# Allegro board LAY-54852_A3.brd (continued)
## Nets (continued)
GND: BH901.1 BH1901.1 BH1902.1 BH1903.1 BH1904.1 BT1001.2(-) C10.2 C22.2 C23.2 C38.2 C101.2 C102.2 C104.2 C105.2 C106.2 C107.2 C108.2 C109.2 C110.2 C111.2 C115.2 C116.2 C118.2 C119.2 C129.2 C130.2 C131.2 C132.2 C133.2 C136.2 C137.2 C138.2 C139.2 C140.2 C142.2 C143.2 C144.2 C145.2 C146.2 C151.2 C152.2 C153.2 C155.2 C201.2 C202.2 C203.2 C204.2 C205.2 C206.2 C207.2 C208.2 C209.2 C210.2 C211.2 C212.2 C213.2 C214.2 C215.2 C216.2 C217.2 C218.2 C219.2 C220.2 C221.2 C222.2 C301.2 C302.2 C303.2 C304.2 C305.2 C306.1 C307.2 C309.1 C401.2 C402.2 C403.2 C404.2 C405.2 C406.2 C408.2 C409.2 C410.2 C411.2 C412.2 C413.1 C414.2 C418.2 C501.2 C502.2 C503.2 C504.2 C505.2 C506.2 C507.2 C508.2 C509.2 C510.2 C511.2 C512.2 C513.2 C514.2 C515.2 C516.2 C517.2 C518.2 C519.2 C520.2 C521.2 C701.1 C702.1 C703.2 C704.2 C705.2 C706.2 C707.2 C708.2 C709.1 C710.2 C711.2 C712.1 C713.1 C714.2 C715.2 C716.2 C717.2 C718.1 C719.2 C720.2 C721.1 C722.2 C723.2 C724.1 C725.2 C726.2 C727.2 C728.2 C729.2 C730.2 C731.2 C801.2 C802.2 C803.2 C804.2 C805.2 C806.2 C807.2 C808.2 C809.2 C902.2 C903.2 C904.2 C905.2 C906.2 C907.2 C908.2 C910.2 C911.2 C912.2 C913.2 C914.2 C915.2 C916.2 C917.2 C918.2 C920.2 C921.2 C922.2 C923.2 C928.2 C930.2 C931.2 C932.2 C933.2 C955.2 C956.2 C1019.2 C1020.2 C1021.2 C1022.2 C1023.2 C1024.2 C1201.2 C1202.2 C1204.2 C1205.2 C1207.2 C1208.2 C1209.2 C1210.2 C1217.2 C1219.2 C1221.1 C1223.2 C1227.1 C1230.2 C1231.2 C1301.2 C1302.2 C1303.2 C1304.2 C1307.2 C1308.2 C1309.2 C1310.2 C1317.2 C1318.2 C1319.2 C1320.2 C1322.2 C1323.2 C1324.2 C1325.2 C1401.2 C1402.2 C1403.2 C1404.2 C1405.2 C1406.2 C1407.2 C1408.2 C1409.2 C1410.2 C1411.2 C1412.2 C1413.2 C1414.2 C1415.2 C1416.2 C1417.2 C1418.2 C1419.2 C1420.2 C1421.2 C1422.2 C1423.2 C1424.2 C1425.2 C1426.2 C1427.2 C1428.2 C1429.2 C1430.2 C1431.2 C1432.2 C1433.2 C1434.2 C1435.2 C1436.2 C1437.2 C1460.2 C1461.2 C1462.2 C1501.2 C1502.2 C1503.2 C1504.1 C1505.2 C1506.2 C1507.2 C1508.2 C1509.2 C1703.2 C1704.2 C1719.2 C1720.2 C1721.2 C1722.2 C1723.2 C1724.2 C1725.2 C1726.2 C1727.2 C1728.2 C1729.2 C1730.2 C1731.2 C1732.2 C1733.2 C1734.2 C1735.2 C1736.2 C1737.1 C1738.2 C1739.2 C1740.2 C1741.2 C1742.2 C1743.2 C1744.1 C1745.2 C1746.2 C1747.2 C1748.2 C1750.2 C1751.2 C1752.2 C1754.2 C1755.2 C1756.2 C1757.2 C1762.2 C1763.2 C1764.2 C1765.2 C1771.2 C1772.2 C1787.1 C1789.2 C1792.2 D302.A D601.C(CATHODE) D901.A D902.C(CATHODE) D1003.2(A2) D1004.2(A2) D1005.2(C2) D1006.2(C2) D1007.2(C2) D1008.2(C2) D1009.2(C2) D1010.2(C2) D1410.C(CATHODE) D1411.C(CATHODE) D1414.C(CATHODE) D1503.3(COM_CATHODE) J301.A12 J301.B12 J301.SH1 J301.SH2 J301.SH3 J301.SH4 J901.2 J1002.6(VSS) J1002.10 J1002.11 J1002.12 J1002.13 J1101.A1 J1101.A12 J1101.B1 J1101.B12 J1101.SH1 J1101.SH2 J1101.SH3 J1101.SH4 J1201.2 J1401.6 J1401.9 J1401.14 J1401.20 J1401.25 J1401.30 J1401.34 J1401.39 J1403.5 J1403.6(B3) J1406.7 J1406.8(B4) J1501.4 J1704.3 J1704.5 J1707.1 J1707.7 J1707.18 J1707.33 J1707.39 J1707.45 J1707.51 J1707.57 J1707.63 J1707.69 J1707.75 J1708.A1 J1708.A12 J1708.B1 J1708.B12 J1708.SH1 J1708.SH2 J1708.SH3 J1708.SH4 Q301.2(SOURCE) Q302.2(SOURCE) Q901.2(SOURCE) Q902.2(SOURCE) Q1401.2(SOURCE) Q1402.2(SOURCE) Q1403.2(SOURCE) Q1404.2(SOURCE) Q1405.2(SOURCE) Q1407.2(SOURCE) Q1408.2(SOURCE) Q1409.2(SOURCE) Q1410.2(SOURCE) Q1411.2(SOURCE) R14.2 R201.2 R204.2 R207.1 R208.1 R303.2 R313.2 R353.1 R354.1 R405.2 R412.1 R413.1 R415.2 R418.2 R423.2 R424.2 R507.2 R508.2 R509.1 R519.2 R520.2 R521.2 R522.2 R523.2 R524.2 R525.2 R526.2 R527.2 R609.2 R610.2 R611.2 R612.2 R718.2 R741.2 R742.2 R743.1 R751.2 R752.2 R827.2 R838.2 R839.2 R840.2 R841.2 R910.2 R911.2 R954.2 R1078.1 R1079.1 R1222.2 R1330.2 R1409.1 R1410.1 R1412.1 R1433.2 R1434.2 R1435.2 R1436.2 R1437.2 R1446.2 R1447.2 R1448.2 R1462.2 R1463.2 R1488.2 R1489.2 R1490.2 R1706.2 R1717.2 R1719.2 R1728.2 R1738.2 R1745.2 R1746.2 R1747.2 R1750.2 R1753.2 R1754.2 R1759.2 R1761.2 R1770.2 R1771.2 R1772.2 R1781.2 R1782.2 R1795.1 R1798.2 R1800.2 R1801.2 R1810.2 R1812.1 R1821.2 R1823.2 R1824.2 SW1401.1 SW1401.2 SW1402.1 SW1402.2 TP615.1(TP) TP617.1(TP) TP1412.1(PIN1) TP1901.1(TP) TP1902.1(PIN1) TP1903.1(PIN1) TP1904.1(PIN1) TP1905.1(TP) TP1907.1(PIN1) TP1908.1(PIN1) TP1909.1(PIN1) TVS901.1 TVS1201.1 TVS1202.1 TVS1203.1 TVS1204.1 TVS1401.1 U58.2 U101.A1 U101.A17 U101.C6 U101.C8 U101.C12 U101.C14 U101.D3 U101.D15 U101.E12 U101.F3 U101.F6 U101.F8 U101.F10 U101.F15 U101.G6 U101.G12 U101.H3 U101.H9 U101.H15 U101.J6 U101.J12 U101.K3 U101.K9 U101.L7 U101.M3 U101.M6 U101.M8 U101.M10 U101.M12 U101.M15 U101.N10 U101.P3 U101.P15 U101.R4(VSS9) U101.R6 U101.R8 U101.R10 U101.R12 U101.R14 U101.U1 U101.U17 U201.A3 U201.A10 U201.AB3 U201.AB5 U201.AB8 U201.AB10 U201.C1 U201.C5 U201.C8 U201.C12 U201.D2 U201.D4 U201.D9 U201.D11 U201.E1 U201.E5 U201.E8 U201.E12 U201.G1 U201.G3 U201.G5 U201.G8 U201.G10 U201.G12 U201.J1 U201.J3 U201.J10 U201.J12 U201.K2 U201.K4 U201.K9 U201.K11 U201.N2 U201.N4 U201.N9 U201.N11 U201.P1 U201.P3 U201.P10 U201.P12 U201.T1 U201.T3 U201.T5 U201.T8 U201.T10 U201.T12 U201.V1 U201.V5 U201.V8 U201.V12 U201.W2 U201.W4 U201.W9 U201.W11 U201.Y1 U201.Y5 U201.Y8(VSS_Y8) U201.Y12 U301.17 U302.C3 U302.D3 U302.E3 U303.B3 U303.D3 U401.5 U401.17 U402.A4 U402.B2 U402.B3 U402.B4 U402.B5 U403.B1(GND) U404.2(V-) U405.3 U411.B3 U411.D3 U501.A6 U501.C4 U501.E7 U501.G5 U501.H10 U501.J5 U501.K8 U501.N2 U501.N5 U501.P4 U501.P6 U502.3 U502.8 U503.3 U503.8 U701.5 U701.43 U701.57 U801.25(VSS) U801.26 U801.33 U802.3 U803.6 U804.6 U805.6 U901.2 U901.10 U902.4 U904.6 U905.6 U906.6 U908.6 U915.A2 U915.B1 U1004.7(VSS) U1004.17 U1202.2 U1301.5 U1301.6 U1301.7 U1301.8 U1302.3 U1302.5 U1302.6 U1302.7 U1302.8 U1304.5 U1304.6 U1304.7 U1304.8 U1305.3 U1305.5 U1305.6 U1305.7 U1305.8 U1306.2 U1307.3 U1308.3 U1309.3 U1401.6 U1401.7 U1403.B1(GND) U1404.10 U1404.11 U1405.2(VSS) U1406.4 U1407.3 U1408.6 U1409.9(VSS) U1409.23 U1409.24 U1409.25 U1410.2 U1501.2 U1702.6 U1702.13 U1706.1 U1706.5 U1706.10 U1706.11 U1706.13 U1706.15 U1706.25 U1706.35 U1706.47 U1706.51 U1707.3 U1708.B1 U1709.B1 U1709.C1 U1709.C7 U1709.D7 U1709.F3 U1709.G5 U1710.10 U1712.41 U1713.10 U1713.11 U1714.2 X1401.2 X1401.4 Y401.2 Y401.4 Y501.2 Y501.4
GND_CHASSIS: C1744.2 J501.10 J501.SH1 J501.SH2 R509.2
VBUS1_DET_3V3: R301.1 U101.B3
VBUS_DBG: J1708.A4 J1708.A9 J1708.B4(VBUS4) J1708.B9 L1702.1 TVS1401.2(A2)
VBUS_IN: C302.1 C303.1 C905.1 C931.1 C932.1 C933.1 C1735.1 R302.2 R904.1 R905.1 R1757.2 R1773.2 R1774.2 U901.1
VBUS_OVLO_TH: R304.2 R1759.1 U302.B3
VBUS_USB_DBG: C1409.1 C1725.1 C1726.1 L1702.2 U1410.1 U1410.3
VCC_3V6: C907.1 R908.1 U901.9
VCC_FT_1V8: C1408.1 C1723.1 C1724.1 L1404.1 U1706.12 U1706.37 U1706.64
VCC_FT_3V3: C1417.1 C1418.1 C1419.1 C1420.1 C1423.1 C1424.1 C1425.1 C1429.1 C1432.1 C1433.1 C1434.1 C1435.1 C1460.1 C1461.1 C1719.1 C1720.1 D1703.C D1704.C L1703.1 L1704.1 R1053.1 R1056.1 R1421.2 R1450.1 R1451.1 R1452.1 R1453.1 R1465.1 R1467.1 R1468.1 R1485.1 R1486.1 R1726.2 R1727.2 R1729.2 R1730.2 R1733.2 R1734.1 R1735.1 R1736.1 R1737.1 R1742.1 R1748.1 R1815.1 R1816.1 U1404.3 U1405.6 U1406.8(VCC) U1407.6 U1408.1 U1409.21 U1706.20 U1706.31 U1706.42 U1706.50 U1706.56 U1713.2(VCCB)
VDD_1V8: C23.1 C115.1 C116.1 C201.1 C202.1 C203.1 C204.1 C205.1 C209.1 C504.1 C505.1 C506.1 C507.1 C719.1 C720.1 C802.1 C922.1 C923.1 C1436.1 C1437.1 C1448.1 C1756.1 D1407.A J1405.1 L102.1 L705.2 L1201.1 L1301.1 Q1406.2(SOURCE) R64.2 R65.2 R501.1 R502.1 R510.1 R746.2 R951.1 R952.1 R956.2 R1441.1 R1459.1 R1460.1 R1756.1 R1767.1 R1779.1 TP707.1(TP) U101.L6 U101.L9 U101.L11 U201.F1 U201.F12 U201.G4 U201.G9 U201.T4 U201.T9 U201.U1 U201.U12 U501.C6 U501.M4 U501.N4 U501.P3 U501.P5 U701.14 U802.5 U904.11 U905.11(VCCB) U906.1 U908.1 U1408.11
VDD_3V3: C22.1 C118.1 C119.1 C155.1 C307.1 C411.1 C501.1 C502.1 C503.1 C714.1 C715.1 C724.2 C801.1 C804.1 C805.1 C806.1 C807.1 C808.1 C809.1 C920.1 C921.1 C955.1 C956.1 C1201.1 C1202.1 C1231.1 C1319.1 C1320.1 C1324.1 C1325.1 C1401.1 C1403.1 C1404.1 C1412.1 C1426.1 C1427.1 C1703.1 C1704.1 C1721.1 C1722.1 C1755.1 C1789.1 C1792.1 D1501.A D1502.A D1703.A J1406.1 J1406.2 L501.1 L502.1 L704.2 L1405.1 R213.1 R306.1 R307.1 R308.1 R309.1 R431.1 R505.1 R506.1 R601.1 R602.1 R603.1 R604.1 R613.1 R705.1 R801.1 R802.1 R804.1 R808.1 R817.1 R863.1 R913.2 R923.1 R935.1 R950.1 R1054.1 R1075.1 R1076.1 R1080.1 R1081.1 R1202.1 R1203.1 R1221.1 R1333.1 R1402.1 R1403.1 R1404.1 R1405.1 R1406.1 R1407.1 R1408.1 R1420.1 R1440.1 R1502.1 R1718.2 R1762.1 R1765.1 R1768.1 R1775.1 R1813.1 R1827.1 TP608.1(TP) TP706.1(TP) U101.E8 U101.H13 U101.K13 U301.3(VDD) U401.3(VDD) U501.E6 U501.F5 U501.J10 U501.K9 U701.21 U701.22 U801.27 U801.31 U803.14(VDD) U804.14(VDD) U805.14(VDD) U904.1 U905.1 U906.11(VCCB) U908.11(VCCB) U915.A1(VCC) U1306.1 U1307.5 U1308.5 U1401.5(VDDIO) U1401.8 U1404.2(VCCB) U1702.14(VDD) U1709.A3 U1709.G3 U1713.3 U1714.3
VDD_5V: C309.2 C413.2 C910.1 C928.1 C930.1 C1219.1 C1733.1 D1402.2 R912.1 R914.1 R1501.2 R1503.2 R1766.1 TP904.1(PIN1) U58.5 U301.12 U401.12 U404.5 U902.7(VOUT) U1202.3
VDD_ANA_0V8: C130.1 C131.1 C132.1 C133.1 R871.2 TP712.1(TP) U101.C4 U101.F13 U101.M13
VDD_ANA_1V8: C142.1 C143.1 C144.1 C145.1 C146.1 L102.2 R111.2 U101.E6 U101.F12 U101.L12 U101.N8
VDD_COIN_3V: BT1001.1 R1072.2 R1082.1
VDD_SNVS_0V8: C102.1 U101.C10
VDD_SOC_0V85: C104.1 C105.1 C106.1 C107.1 C108.1 C109.1 C110.1 C111.1 C707.1 C708.1 L702.2 R701.1 R709.1 R711.2 TP703.1(TP) U101.G7 U101.G9 U101.G11 U101.H7 U101.H11 U101.K7 U101.K11
VINT: C706.1 U701.4
ADC_IN0: C1413.1 R1442.2 TP408.1(PIN1) U101.B8
ADC_IN1: C1414.1 R1444.2 TP409.1(PIN1) U101.A8
ADCDAT1: R1208.2 U1709.D2
AUD_5V: L1205.1 U1202.1 U1202.5(OUT2)
AUD_NINT: R845.2 R1204.1 R1221.2
AUD_PWREN: R831.2 R1219.1
AUD_SCL: R1212.2 U1709.F1
AUD_SDA: R1211.2 U1709.E2
BCLK1: R1206.2 U1709.E1
BT_MODE0: R1731.2 U1404.6
BT_MODE1: R1732.2 U1404.7
BT_MODE2: R1418.2 U1404.8
BT_MODE3: R1419.2 U1404.9
BUF_POR: R808.2 R811.1 U802.4(Y)
BYPASS1: C1737.2 U401.4
CAN1_RX: R1509.1 U1702.4
CAN1_TX: R1508.1 U1702.1
CAN_H: C1504.2 D1503.1 J1501.2 L1501.2 R1504.2 R1507.2
CAN_L: C1509.1 D1503.2 J1501.3 L1501.3 R1510.2 R1511.1
CAN_RX: R1505.2 R1509.2 U1501.4
CAN_STBY: R837.2 R1512.2 U1501.8
CAN_TX: R1506.2 R1508.2 U1501.1
CAN_VDD_5V: C1501.1 C1502.1 R1501.1 U1501.3
CAN_VIO_3V3: C1503.1 R1502.2 R1512.1 U1501.5(VIO)
CANH: L1501.1 R1507.1 U1501.7
CANL: L1501.4 R1510.1 U1501.6
CLKIN1: R415.1 TP411.1(PIN1) U101.A6
CLKIN2: R423.1 TP412.1(PIN1) U101.B6
CLKOUT2: TP1948.1(PIN1) U1709.E4
CLKOUT5: TP1950.1(PIN1) U1709.G6
CON_JTAG_NRST: D1408.C D1409.C J1704.10(B5) R1461.2
CPCA: C1761.1 U1709.B6
CPCB: C1761.2 U1709.B7
CPVOUTN: C1762.1 U1709.A7
CPVOUTP: C1763.1 U1709.A6
DACDAT1: R1207.2 U1709.D1
DBG_ACC: TP1926.1(PIN1) U401.9
DCIN_15V: J901.1 R905.2
DMIC_PDM_CLK: U1309.2 U1702.16
DMIC_PDM_DATA0: U1307.4(Y) U1702.3
DMIC_PDM_DATA1: U1308.4(Y) U1702.9
DRAM_CA0_A: TP219.1(PIN1) U101.F1 U201.H2
DRAM_CA1_A: U101.E2 U201.J2
DRAM_CA2_A: U101.D2 U201.H9
DRAM_CA3_A: U101.C1 U201.H10
DRAM_CA4_A: U101.B2 U201.H11
DRAM_CA5_A: U101.A2 U201.J11
DRAM_CK_C_A: R205.2 U101.B1 U201.J9
DRAM_CK_T_A: R205.1 U101.C2 U201.J8
DRAM_CKE0_A: R207.2 U101.G1 U201.J4
DRAM_CKE1_A: R208.2 U101.F2 U201.J5
DRAM_DATA0_A: TP206.1(PIN1) U101.L2 U201.F4
DRAM_DATA1_A: TP207.1(PIN1) U101.L1 U201.E4
DRAM_DATA2_A: TP208.1(PIN1) U101.K2 U201.C4
DRAM_DATA3_A: TP209.1(PIN1) U101.K1 U201.B4
DRAM_DATA4_A: TP202.1(PIN1) U101.J1 U201.B2
DRAM_DATA5_A: TP203.1(PIN1) U101.H2 U201.C2
DRAM_DATA6_A: TP204.1(PIN1) U101.H1 U201.E2
DRAM_DATA7_A: TP205.1(PIN1) U101.G2 U201.F2
DRAM_DATA8_A: TP212.1(PIN1) U101.T2 U201.E11
DRAM_DATA9_A: TP213.1(PIN1) U101.U2 U201.F11
DRAM_DATA10_A: TP211.1(PIN1) U101.T1 U201.C11
DRAM_DATA11_A: TP210.1(PIN1) U101.R2 U201.B11
DRAM_DATA12_A: TP216.1(PIN1) U101.N1 U201.C9
DRAM_DATA13_A: TP217.1(PIN1) U101.N2 U201.B9
DRAM_DATA14_A: TP215.1(PIN1) U101.M2 U201.E9
DRAM_DATA15_A: TP214.1(PIN1) U101.M1 U201.F9
DRAM_DMI0_A: TP201.1(PIN1) U101.J2 U201.C3
DRAM_DMI1_A: U101.R1 U201.C10
DRAM_NCS0_A: TP218.1(PIN1) U101.D1 U201.H4
DRAM_NCS1_A: U101.E1 U201.H3
DRAM_NRESET: R102.1 R201.1 U101.F4 U201.T11
DRAM_SDQS0_C_A: U101.K4 U201.E3
DRAM_SDQS0_T_A: U101.M4 U201.D3
DRAM_SDQS1_C_A: U101.P2 U201.E10
DRAM_SDQS1_T_A: U101.P1 U201.D10
DRAM_ZN: R204.1 U101.H4
DRAM_ZQ0: R209.2 U201.A5
EMMC_VDDIM: C508.1 C509.1 U501.C2
EN_SNK: R411.2 U402.F1
EN_SRC: R410.2 U402.G1
ENET1_MDC: R503.1 U101.T8
ENET1_MDIO: R1779.2 R1780.1 U101.U7
ENET1_NINT: R505.2 U804.16 U1712.31
ENET1_NRST: R506.2 R826.2 U1712.12
ENET1_RD0: R517.2 R526.1 U101.U5 U1712.25
ENET1_RD1: R518.2 R527.1 U101.T6 U1712.24
ENET1_RD2: R514.2 R522.1 U101.U6 U1712.23
ENET1_RD3: R515.2 R523.1 U101.T7 U1712.22
ENET1_RX_CTL: R525.1 U101.T5 U1712.26
ENET1_RXC: C519.1 R516.2 R524.1 U101.U4 U1712.27
ENET1_TD0: TP221.1(PIN1) U101.U9 U1712.18
ENET1_TD1: U101.R9 U1712.17
ENET1_TD2: U101.U10 U1712.16
ENET1_TD3: U101.T10 U1712.15
ENET1_TX_CTL: U101.T9 U1712.19
ENET1_TXC: TP220.1(PIN1) U101.U8 U1712.20
ETH1_10/100M_LINK/ACTIVE: J501.13 R504.1
ETH1_1000M_LINK/ACTIVE: J501.11 R507.1 R529.1
ETH1_AVDD1V0: C515.1 C516.1 C517.1 C518.1 R530.2 U1712.3 U1712.8 U1712.38
ETH1_AVDD3V3: C1742.1 C1743.1 L502.2 U1712.11 U1712.40
ETH1_CLK125_OUT: TP1933.1(PIN1) U1712.35
ETH1_CT: C1738.1 J501.1
ETH1_DVDD1V0: C513.1 C514.1 R531.2 U1712.21
ETH1_DVDD3V3: C1739.1 C1740.1 L501.2 R512.1 R513.1 R529.2 U1712.29
ETH1_LED0/CFG_EXT: R504.2 R512.2 R519.1 U1712.32
ETH1_LED1/CFGLDO0: C520.1 J501.14 R521.1 U1712.33
ETH1_LED2/CFGLDO1: C521.1 J501.12 R513.2 R520.1 U1712.34
ETH1_TRX0_N: J501.3 U503.2 U503.9 U1712.2
ETH1_TRX0_P: J501.2 U503.1 U503.10(NC4) U1712.1
ETH1_TRX1_N: J501.5 U503.5 U503.6 U1712.5
ETH1_TRX1_P: J501.4 U503.4 U503.7 U1712.4
ETH1_TRX2_N: J501.7 U502.2 U502.9 U1712.7
ETH1_TRX2_P: J501.6 U502.1 U502.10(NC4) U1712.6
ETH1_TRX3_N: J501.9(TRD4-) U502.5 U502.6 U1712.10
ETH1_TRX3_P: J501.8 U502.4 U502.7 U1712.9
ETH1_VDD1V0: C511.1 C512.1 R530.1 R531.1 U1712.30
ETH1_VDDIO: C1745.1 C1746.1 R510.2 R514.1 R515.1 R516.1 R517.1 R518.1 U1712.28
ETH1_XTALI: C510.1 R511.2 U1712.36 Y501.3
ETH1_XTALO: C1741.1 R511.1 U1712.37(XTAL_OUT/ EXT_CLK) Y501.1
EXP3V3_EN: R858.2 R1825.1
EXP5V_EN: R16.1 R806.2
EXP_3V3: C1402.1 C1405.1 L1401.1 U1714.1 U1714.5(OUT2)
EXP_5V: C38.1 C1406.1 C1407.1 L1402.2 U58.1(OUT)
EXP_GPIO_IO08: J1401.24 U805.1
EXP_GPIO_IO09: J1401.21 U805.4
EXP_GPIO_IO10: J1401.19 U805.8
EXP_GPIO_IO11: J1401.23 U805.11
EXP_GPIO_IO12: J1401.32 R1438.1 U803.1
EXP_GPIO_IO16: R856.2 R1829.1 U804.1
EXP_GPIO_IO17: J1401.11 U804.4
EXP_GPIO_IO18: R855.2 R1829.2 U803.4
EXP_GPIO_IO19: J1401.35 R745.2 U803.8
EXP_GPIO_IO20: J1401.38 U803.11
EXP_GPIO_IO21: J1401.40 U804.8
EXP_NIRQ: R813.1 U101.T4
EXP_SEL: R836.2 R838.1 U803.15 U804.15 U805.15
EXT1_PWREN: R825.2 R922.1
FRS_EN: U401.1 U402.B6
FT_BMODE_DIR: R1728.1 U1404.4 U1404.5 U1409.14
FT_BOOT_MODE0: R1731.1 U1409.1
FT_BOOT_MODE1: R1732.1 U1409.2
FT_BOOT_MODE2: R1418.1 U1409.3
FT_BOOT_MODE3: R1419.1 U1409.4
FT_EECLK: R1428.2 U1706.62
FT_EECS: R1740.2 U1706.63
FT_EEDATA: R1739.2 U1706.61
FT_IO_NINT1: R1487.1 U1706.30
FT_IOEXP2_SCL: R1470.2 U1409.19
FT_IOEXP2_SDA: R1469.2 U1409.20
FT_NPWREN: R1464.1 R1749.1 TP1407.1(PIN1) U1706.60
FT_NSUSPEND: R1744.1 TP1408.1(PIN1) U1706.36
FT_ONOFF: R1746.1 U1406.3 U1409.12
FT_OSCI: C1428.1 U1706.2 X1401.1
FT_OSCO: C1430.1 U1706.3 X1401.3
FT_POR_B: R1747.1 U1406.6 U1409.10
FT_RC_SEL: R1751.1 U1409.13
FT_SCL: R1470.1 R1726.1 TP1912.1(PIN1) U1706.26
FT_SD_CD: R1053.2 U1409.16 U1707.1
FT_SD_PWREN: R1056.2 R1057.1 U1409.15
FT_SDA: R1469.1 R1727.1 TP1913.1(PIN1) U1706.27 U1706.28
FT_SYS_NRST: R1745.1 U1406.1 U1409.11
FT_TST0: R1455.1 U1706.21
FT_TST1: R1457.1 U1706.22
FT_TST2: R1456.1 U1706.23
FT_TST3: R1458.1 U1706.24
FT_USB_DN: U1403.C1 U1706.7
FT_USB_DP: U1403.C2 U1706.8
FTA_TCK: U1408.2 U1706.16
FTA_TDI: U1408.3 U1706.17
FTA_TDO: U1408.5 U1706.18
FTA_TMS: U1408.4 U1706.19
FTC_RXD: D1404.C(CATHODE) R1819.1 U1706.39
FTC_TXD: D1403.C(CATHODE) R1817.1 U1706.38
FTD_CTS: TP1406.1(PIN1) U1706.54
FTD_RTS: TP1405.1(PIN1) U1706.53
FTD_RXD: D1405.C(CATHODE) R1820.1 U1706.52
FTD_TXD: D1406.C(CATHODE) R1818.1 U1706.48
GPIO_IO00: J1401.27 R1415.2 U101.B16
GPIO_IO01: J1401.28 R1417.2 U101.B17
GPIO_IO02: J1401.3 R1414.2 U101.C16
GPIO_IO03: J1401.5 R1416.2 U101.C17
GPIO_IO04: J1401.7 R1429.1 U101.D16
GPIO_IO05: J1401.29 U101.D17
GPIO_IO06: J1401.31 U101.E16
GPIO_IO07: J1401.26 U101.E17
GPIO_IO08: U101.K14 U805.2
GPIO_IO09: U101.F16 U805.5
GPIO_IO10: U101.F17 U805.7
GPIO_IO11: U101.G16 U805.10
GPIO_IO12: U101.F14 U803.2
GPIO_IO13: J1401.33 R1439.1 U101.G17
GPIO_IO14: J1401.8 U101.H16
GPIO_IO15: J1401.10 U101.H17
GPIO_IO16: U101.J16 U804.2
GPIO_IO17: U101.K15 U804.5
GPIO_IO18: U101.M14 U803.5
GPIO_IO19: U101.J17 U803.7
GPIO_IO20: U101.K16 U803.10
GPIO_IO21: U101.K17 U804.7
HP_DET: R812.2 R1822.1
HP_J_D: J1201.5 R1202.2 R1822.2 TVS1203.2(A2)
HP_J_L: C1771.1 J1201.4 L1202.2 TVS1202.2(A2)
HP_J_R: C1772.1 J1201.3 L1203.2 TVS1204.2(A2)
HP_MICIN: C1788.2 J1201.1 R1809.2 TVS1201.2(A2)
HPOUTL: C1769.1 L1202.1 R1823.1 U1709.B5
HPOUTR: C1770.1 L1203.1 R1810.1 U1709.A5
I2C1_SCL: R163.2 R307.2 R433.1 R717.1 R828.1 R1008.1 R1212.1 R1443.1 U101.A12
I2C1_SCLL: J1707.60 R65.1 R713.2 R930.2
I2C1_SDA: R164.2 R306.2 R432.1 R719.1 R830.1 R1009.1 R1211.1 R1445.1 U101.B12
I2C1_SDAL: J1707.58 R64.1 R712.2 R931.2
I2C2_SCL: R309.2 R714.1 R820.1 U101.A11
I2C2_SDA: R308.2 R715.1 R824.1 U101.B11
I2C3_SCL: R1015.1 R1405.2 R1413.1 R1417.1
I2C3_SDA: R1016.1 R1406.2 R1411.1 R1415.1
I2C4_SCL: R1017.1 R1407.2 R1416.1
I2C4_SDA: R1018.1 R1408.2 R1414.1
I3C1_SCL: R163.1 R861.1 R1404.2 R1413.2 U1401.13
I3C1_SDA: R164.1 R862.1 R1401.2 R1403.2 R1411.2 U1401.14
I3C_PUR: R1401.1 TP1401.1(PIN1)
I3C_TEMP_NINT: R744.2 R860.2
I.MX_SPI_CLK/UART_RTSO: R944.2 U905.8 U906.4
I.MX_SPI_CS/UART_TXD: R938.2 R945.2 U905.10 U906.2
I.MX_SPI_MISO/UART_RXD: R943.2 U905.7 U906.5
I.MX_SPI_MOSI/UART_CTSI: R941.2 R942.2 U905.9 U906.3
ILIM_5V_VBUS: TP1927.1(PIN1) U401.6
IMU_INT1: D1401.A U804.9
IN1R: C1787.2 U1709.D4
IN3R: C1788.1 U1709.F6
IOEXP_IO22: R854.1
IOEXP_IO23: R853.2
IOEXP_IO24: J1401.18(B9) R851.2
IOEXP_IO25: J1401.22 R850.2
IOEXP_IO27: J1401.13 R852.2
JTAG_TCK: J1704.4 R405.1 R416.1 TP1922.1(PIN1) U101.U3 U1408.10
JTAG_TDI: J1704.8 R417.1 R1460.2 TP1920.1(PIN1) U101.P8 U1408.9
JTAG_TDO: J1704.6 R414.1 TP1923.1(PIN1) U101.T3 U1408.7
JTAG_TMS: J1704.2 R419.1 R1459.2 TP1921.1(PIN1) U101.P6 U1408.8(YB3)
LD_I2C_SCL: R420.1 U402.B1
LD_I2C_SDA: R421.1 R434.1 U402.C1
LD_NFLT: R1775.2 R1776.1 U401.11
LD_NINT: R1776.2 U402.D1
LED_B: Q1401.3 R1424.2
LED_G: Q1402.3 R1423.2
LED_R: Q1403.3 R1425.2
LPD4/X_VDD2_1V1: C136.1 C137.1 C138.1 C139.1 C140.1 C206.1 C207.1 C208.1 C210.1 C211.1 C212.1 C213.1 C214.1 C722.1 C723.1 L706.2 R210.1 R702.1 TP708.1(TP) U101.K5 U101.M5 U101.N6 U101.P4 U201.A4 U201.A9 U201.AB4 U201.AB9 U201.F5 U201.F8 U201.H1 U201.H5 U201.H8 U201.H12 U201.K1 U201.K3 U201.K10 U201.K12 U201.N1 U201.N3 U201.N10 U201.N12 U201.R1 U201.R5 U201.R8 U201.R12 U201.U5 U201.U8 U701.52
LPD4/X_VDDQ_0V6: C151.1 C152.1 C153.1 C215.1 C216.1 C217.1 C218.1 C219.1 C220.1 C221.1 C222.1 R209.1 R211.2 R702.2 R704.2 TP702.1(TP) U101.F5 U101.H5 U201.AA3 U201.AA5 U201.AA8 U201.AA10 U201.B3 U201.B5 U201.B8 U201.B10 U201.D1 U201.D5 U201.D8 U201.D12 U201.F3 U201.F10 U201.U3 U201.U10 U201.W1 U201.W5 U201.W8 U201.W12
LPD4X_VDDQ_0V6: C703.1 C705.1 L701.2 R704.1 U701.44
LRCLK1: R1205.2 U1709.D3
LS_OE: R935.2 R1812.2 U905.12 U906.12
M2_LED1#: D1705.C(CATHODE) J1707.6
M2_LED2#: D1706.C(CATHODE) J1707.16
M2_NALERT: R818.2 R932.2 R936.2
M2_NDIS1: J1707.56 R835.2 R903.1
M2_NDIS2: J1707.54(W\_\D\I\S\A\B\L\E\2\) Q902.1 R832.2 R953.1
M2_NRST: J1707.52 R833.2
M2_PCM_CLK: J1707.8 R946.2
M2_PCM_IN: J1707.12 R949.2
M2_PCM_OUT: J1707.14 R948.2
M2_PCM_SYNC: J1707.10 R947.2
M2_PWRON: C1754.1 R903.2 R922.2 R950.2 R1781.1 U1710.5
M2_SD_NWAKE: J1707.21 R1793.2 TP918.1(PIN1)
M2_UART_NWAKE: J1707.20 R809.2 R924.2
M2_USB_DN: J1707.5 TP1935.1(PIN1)
M2_USB_DP: J1707.3 TP1934.1(PIN1)
M33_NMI: TP1701.1(PIN1) U1702.8
MIC/CAN_SEL: R829.2 R1706.1 U1702.15
MICBIAS: C1208.1 R1809.1 U1709.A4
MX_POR_B: C401.1 R402.2 R404.2 TP402.1(PIN1) U101.B7
NVCC_BBSM_1V8: C101.1 C727.1 J1403.1 J1403.2 R401.1 R402.1 R403.1 R703.1 R1431.1 R1432.1 TP709.1(TP) U101.E10 U701.3
NVCC_SD2: C129.1 C731.1 C1019.1 R310.1 R311.1 R312.1 R1052.1 TP713.1(TP) U101.N12 U701.55 U1707.5
ODT_CA_A: R210.2 U201.G2
ONOFF: C1411.1 R403.2 R1426.2 R1741.2 TP401.1(PIN1) U101.D10
PCIE_CLKN: J1707.49 TP909.1(PIN1)
PCIE_CLKP: J1707.47 TP908.1(PIN1)
PCIE_NCLKREQ: J1707.53 TP910.1(PIN1)
PCIE_NWAKE: J1707.55 R917.2 TP920.1(PIN1)
PCIE_RXN: J1707.43 TP907.1(PIN1)
PCIE_RXP: J1707.41 TP906.1(PIN1)
PCIE_TXN: J1707.37 TP905.1(PIN1)
PCIE_TXP: J1707.35 TP911.1(PIN1)
PD_BYPASS: C306.2 U301.4
PD_DBG_ACC: TP308.1(PIN1) U301.9
PD_EN_SINK: R1760.1 U301.2
PD_EN_SRC: TP306.1(PIN1) U301.16
PD_FRS_EN: TP307.1(PIN1) U301.1
PD_ILIM_5V_VBUS: TP309.1(PIN1) U301.6
PD_LD_NFLT: R1764.1 U301.11
PD_USB_CC1: U301.13 U303.A2
PD_USB_CC2: U301.14 U303.B2 U303.C1 U303.C2
PD_USB_VBUS_IN: R302.1 R1757.1 TP302.1(PIN1) U302.A1 U302.B1 U302.C1 U302.D1
PD_VBUS_PG: Q302.1 R1763.2 TP304.1(PIN1) U302.A2
PDM_CLK: R1703.1 U101.A16
PDM_DATA0: R1704.1 U101.A10
PDM_DATA1: R1705.1 U101.B10
PMIC_32K_OUT: R406.1 R958.2 U701.7
PMIC_NINT: R817.2 R822.2 U701.13
PMIC_ON_REQ: Q1409.1 R401.2 R418.1 R707.1 R915.1 TP403.1(PIN1) U101.A7
PMIC_STBY_REQ: Q1410.1 R424.1 R708.1 TP404.1(PIN1) U101.C9
POR_B: D1408.A Q1408.1 R404.1 R1743.2 U701.9 U802.2
RC_BT_MODE0: R608.1 R609.1 SW601.7 U1404.15
RC_BT_MODE1: R607.1 R610.1 SW601.5 U1404.14
RC_BT_MODE2: R606.1 R611.1 SW601.3 U1404.13
RC_BT_MODE3: R605.1 R612.1 SW601.1 U1404.12
RC_NSEL: D1413.C(CATHODE) Q1405.3 R1815.2 U1404.1 U1404.16 U1408.12
RC_SEL: D1412.C(CATHODE) Q1405.1 R1449.2 R1752.2 R1754.1
REG_FT_1V8: C1421.1 C1422.1 L1404.2 U1706.49(VREGOUT)
RTC_CLKO: R959.2 TP1021.1(PIN1) U1004.6
RTC_NINTA: R807.2 R1075.2 R1084.1 TP1019.1(PIN1) U1004.13
SAI1_RXD0: R909.1 U101.B14
SAI1_TXC: R1784.1 U101.B15
SAI1_TXD0: R605.2 R1786.1 TP604.1(TP) U101.A15
SAI1_TXFS: R606.2 R1785.1 TP603.1(TP) U101.A14
SAI3_MCLK: R1209.1 U804.3
SAI3_RXC: R1206.1 U803.3
SAI3_RXD: R1208.1 U803.12
SAI3_RXFS: R1205.1 U803.16
SAI3_TXD: R1207.1 U803.9
SD1_CLK: TP503.1(PIN1) U101.U11 U501.M6
SD1_CMD: R502.2 TP502.1(PIN1) U101.T11 U501.M5
SD1_DATA0: R501.2 TP501.1(PIN1) U101.T13 U501.A3
SD1_DATA1: U101.T14 U501.A4
SD1_DATA2: U101.T15 U501.A5
SD1_DATA3: U101.U13 U501.B2
SD1_DATA4: U101.T12 U501.B3
SD1_DATA5: U101.U14 U501.B4
SD1_DATA6: U101.U15 U501.B5
SD1_DATA7: U101.U16 U501.B6
SD1_STROBE: TP505.1(PIN1) U101.U12 U501.H5
SD2_CLK: R1061.1 U101.M16
SD2_CMD: R311.2 R1060.1 U101.M17
SD2_DATA0: R310.2 R1062.1 U101.N17
SD2_DATA1: R1063.1 U101.N16
SD2_DATA2: R1064.1 U101.L17
SD2_DATA3: R1065.1 U101.L16
SD2_NCD: R1051.1 R1052.2 U101.P12 U1707.4(Y)
SD2_NDET: D1004.1 J1002.9 R1051.2 R1054.2 TP1914.1(PIN1) U1707.2
SD2_NRST: R312.2 R723.2 U101.P10
SD2_VSEL: U101.P14 U701.29
SD3_CLK: J1707.9 TP912.1(PIN1) U101.T16
SD3_CMD: J1707.11 R952.2 TP913.1(PIN1) U101.T17
SD3_DATA0: J1707.13 R951.2 TP914.1(PIN1) U101.R16
SD3_DATA1: J1707.15 TP1936.1(PIN1) U101.R17
SD3_DATA2: J1707.17 TP1937.1(PIN1) U101.P16
SD3_DATA3: J1707.19 TP917.1(PIN1) U101.P17
SD3_NRST: J1707.23 R821.2 R827.1 TP919.1(PIN1)
SD3_NWAKE: R810.2 R923.2 R1793.1
SD_CLK: D1006.1 J1002.5 R1061.2
SD_CMD: D1005.1 J1002.3 R1060.2
SD_DATA0: D1007.1 J1002.7 R1062.2
SD_DATA1: D1008.1 J1002.8 R1063.2
SD_DATA2: D1009.1 J1002.1 R1064.2
SD_DATA3: D1010.1 J1002.2 R1065.2
SPI3_CLK: U805.12 U905.4 U906.8
SPI3_CS0: U805.16 U905.2 U906.10
SPI3_MISO: U805.3 U905.5 U906.7
SPI3_MOSI: U805.9 U905.3 U906.9
SPK_LN: R1216.1 U1709.B3
SPK_LP: R1214.1 U1709.A1
SPK_RN: R1220.1 U1709.C3
SPK_RP: R1218.1 U1709.B2
SPKOUTLN: C1218.2 C1221.2 R1216.2 TP1943.1(PIN1)
SPKOUTLP: C1217.1 C1218.1 R1214.2 TP1942.1(PIN1)
SPKOUTRN: C1224.2 C1227.2 R1220.2 TP1945.1(PIN1)
SPKOUTRP: C1223.1 C1224.1 R1218.2 TP1944.1(PIN1)
STAR_I2C_SCL: J1406.3 J1406.4 R1443.2
STAR_I2C_SDA: J1406.5 J1406.6 R1445.2
SUSCLK: J1707.50 R919.1
SYS_EN: D301.C(CATHODE) R352.2 R355.2
SYS_NRST: C1410.1 D1409.A R706.1 R1085.2 R1427.2 R1430.2 TP915.1(TP)
TAMPER0: J1403.3 R1431.2 R1436.1 TP405.1(PIN1) U101.D6
TAMPER1: J1403.4 R1432.2 R1437.1 TP406.1(PIN1) U101.D8
TCPC1_NINT: R431.2 R823.1 U401.10
TCPC_NINT: R805.2 R1765.2 TP310.1(PIN1) U301.10
TEMP_SCL: R861.2 U915.B2
TEMP_SDA: R862.2 U915.C2
UART1_RXD: R1720.2 TP612.1(TP) U101.B13
UART1_TXD: R608.2 R1723.2 TP601.1(TP) TP610.1(TP) U101.A13
UART2_RXD: R1721.2 TP616.1(TP) U101.D14
UART2_TXD: R607.2 R1724.2 TP602.1(TP) TP614.1(TP) U101.D12
UART5_CTSI: J1707.34 R416.2
UART5_RTSO: J1707.36 R419.2
UART5_RXD: J1707.22 R417.2
UART5_TXD: J1707.32 R414.2
USB1_CC1: U401.13 U411.A2
USB1_CC2: U401.14 U411.B2 U411.C1 U411.C2
USB1_DN: TP611.1(TP) U101.A4 U403.C1
USB1_DP: TP613.1(TP) U101.B4 U403.C2
USB1_ID: R1767.2 TP1924.1(PIN1) U101.D4
USB1_VBUS_3V3: R301.2 R1768.2 U404.1
USB1_VBUS_IN: C407.2 R1773.1 R1774.1 TP1925.1(PIN1) U402.C6 U402.D6 U402.E6 U402.F6 U402.G6
USB_CC1_PD: J301.A5 R350.1 R358.1 TP301.1(PIN1)
USB_CC1_PD_OVP: R350.2 R356.2 U303.A1
USB_CC2_PD: J301.B5 R351.1 R359.1 TP303.1(PIN1)
USB_CC2_PD_OVP: R351.2 R357.2 U303.B1
USB_DBG_CC1: J1708.A5 R1488.1
USB_DBG_CC2: J1708.B5 R1489.1
USB_DBG_DN: J1708.A7 J1708.B7 U1403.A1
USB_DBG_DP: J1708.A6 J1708.B6 U1403.A2
USB_I2C_SCL: R420.2 R1008.2 R1015.2 R1017.2 R1073.1 R1777.2 U301.8
USB_I2C_SDA: R421.2 R1009.2 R1016.2 R1018.2 R1074.1 R1778.2 U301.7
USB_PD_VBUS: F301.1 J301.A9 J301.B9(VBUS2)
USB_PD_VBUS_F: C301.1 D401.A F301.2 R304.1 R305.1 U301.15 U302.B2 U302.C2 U302.D2 U302.E1 U302.E2
USBC_CC1: J1101.A5 TP1928.1(PIN1) U411.A1
USBC_CC2: J1101.B5 TP1929.1(PIN1) U411.B1
USBC_DN: J1101.A7 J1101.B7 U403.A1
USBC_DP: J1101.A6 J1101.B6 U403.A2
USBC_EN_SNK1: R411.1 U401.2
USBC_EN_SRC1: R410.1 U401.16
USBC_I2C_SCL: R1777.1 U401.8
USBC_I2C_SDA: R1778.1 U401.7
USBC_SBU1: J1101.A8 TP1930.1(PIN1)
USBC_SBU2: J1101.B8 TP1931.1(PIN1)
USBC_VBUS: F401.1 J1101.A4 J1101.A9 J1101.B4(VBUS4) J1101.B9 TP609.1(TP)
USBC_VBUS_F: C1734.1 D402.A F401.2 R360.1 R1769.1 R1770.1 U401.15 U402.C2 U402.C3 U402.C4 U402.C5 U402.D4 U402.D5 U402.E4 U402.E5 U402.F4 U402.F5 U402.G4 U402.G5
VBBS: C1021.1 U1004.14
VCAN_5V: C1505.1 C1506.1 J1501.1 R1503.1
VEN_SPI_CLK/UART_RTSO: J1707.42 R944.1
VEN_SPI_FRM/UART_CTSI: R941.1 R945.1 R957.2
VEN_SPI_RXD/UART_SIN: J1707.40 R943.1
VEN_SPI_TXD/UART_SOUT: J1707.38 R938.1 R942.1
VLDO1_3V3: C410.1 U402.A5(VLDO)
VLDO3_1V8: C729.1 R111.1 TP711.1(TP) U701.54
VLDO_3V3: C305.1 C408.1 C412.1 C418.1 D1011.A D1012.A R1077.1 R1758.1 R1763.1 U303.A3(VSYS) U402.A1 U405.1(OUT) U411.A3(VSYS)
VMIC_1V8: C1301.1 C1302.1 C1303.1 C1304.1 C1307.1 C1308.1 C1309.1 C1310.1 C1317.1 C1318.1 C1462.1 L1301.2 L1405.2 R1814.2 TP1306.1(PIN1) U1301.3 U1301.4(VDD) U1302.4(VDD) U1304.3 U1304.4(VDD) U1305.4(VDD) U1309.5
VPCIE_3V3: C912.1 C913.1 C914.1 C915.1 C916.1 C917.1 C918.1 C1749.1 C1750.1 C1751.1 C1752.1 C1753.2 C1757.1 J1707.2 J1707.4 J1707.72 J1707.74 L1403.1 L1705.2 R902.1 R917.1 R918.1 R924.1 R936.1 R1790.2 R1791.2 U1710.2
VRPI_3V3: J1401.1 J1401.17 L1401.2 L1403.2
VRPI_5V: J1401.2 J1401.4 L1402.1
VSD2_3V3: C1731.1 C1732.1 D1003.1 J1002.4 R1055.2 TP1919.1(PIN1) U1708.A1(VOUT)
VSD_3V3: C725.1 C1020.1 R1055.1 U701.23 U1708.A2
VSYS_5V: C406.1 C701.2 C702.2 C704.1 C709.2 C712.2 C713.2 C718.2 C721.2 C726.1 C902.1 C903.1 C904.1 C908.1 C911.1 C1736.1 C1747.1 C1748.1 L901.2 R906.1 R1783.1 TP607.1(TP) U402.D2 U402.D3 U402.E2 U402.E3 U402.F2 U402.F3 U402.G2 U402.G3 U701.16 U701.17 U701.18 U701.33 U701.34 U701.35 U701.47 U701.48 U701.49 U701.53 U701.56 U901.5(VOUT) U902.1 U902.3 U902.8 U1710.8 U1710.11(VIN2)
VTREF: J1704.1 R1454.2
WDOG_B: Q1407.1 Q1411.1 R710.1 TP916.1(TP) U101.H14
XIN_32K: C716.1 QZ701.2 R720.1 U701.10
XOUT_32K: C717.1 QZ701.1 R720.2 U701.11(XTAL_OUT)
XTALI_24M: C404.1 R409.1 TP410.1(PIN1) U101.A9 Y401.1
XTALI_32K: R406.2 R407.1 TP407.1(PIN1) U101.A5
XTALO_24M: C405.1 R409.2 U101.B9 Y401.3
XTALO_32K: C403.1 QZ401.1 R408.2 U101.B5
N111682856: C1507.1 R1504.1 S1501.2
N111682880: D1501.C(CATHODE) R1505.1
N111682886: D1502.C(CATHODE) R1506.1
N111683153: C1508.1 R1511.2 S1501.1(NC)
N111686445: R901.1 U901.8
N111686449: C901.1 R901.2
N111686466: C901.2 L901.1 U901.7
N111686641: C906.1 D901.C(CATHODE) R904.2 R907.1 TVS901.2(A2)
N111686683: R907.2 U901.12
N111686689: R906.2 R910.1 U901.11
N111686749: R908.2 R911.1 U901.6
N112168459: R1402.2 U1401.12
N112168530: TP1402.1(PIN1) U1401.11
N112168572: R1409.2 U1401.1
N112168574: TP1403.1(PIN1) U1401.10
N112168590: R1410.2 U1401.2
N112168603: R1412.2 U1401.3
N112168605: TP1404.1(PIN1) U1401.9
N112168607: D1401.C(CATHODE) R1420.2 U1401.4
N112179037: J1401.37 J1710.2
N112179124: J1401.36 R856.1
N112179125: J1401.12 R855.1
N112179128: J1401.16 R853.1
N112247759: C803.1 R804.2 R811.2 U801.28
N112248110: R813.2 R823.2 U801.32
N112248290: R801.2 R824.2 R830.2 U801.30
N112248296: R802.2 R820.2 R828.2 U801.29
N113364863: J1405.6 J1405.8(B4) R1444.1
N113365543: J1405.3 R1440.2 R1446.1
N113365548: J1405.5 R1441.2 R1447.1
N113409056: R1426.1 SW1401.3 SW1401.4(B2)
N113409060: R1427.1 SW1402.3 SW1402.4(B2)
N113524078: C402.1 QZ401.2 R407.2 R408.1
N113526638: L701.1 U701.45 U701.46
N113526990: L702.1 U701.36 U701.37
N113527145: R701.2 R711.1 U701.38
N113527183: C710.1 C711.1 L703.2 R709.2 R716.1
N113527270: L703.1 U701.31 U701.32
N113527381: R716.2 R718.1 U701.30
N113527504: L704.1 U701.19 U701.20
N113527663: L705.1 U701.15
N113527832: L706.1 U701.50 U701.51
N113528020: R723.1 U701.12
N113528254: C728.1 TP710.1(TP) U701.2
N113528336: C730.1 R871.1 U701.1
N114502549: R1703.2 U1702.2
N114502556: R1704.2 U1702.5
N114502597: R1705.2 U1702.7
N114579559: R805.1 U801.1
N114579565: R807.1 U801.2
N114579571: R806.1 U801.3
N114579577: R809.1 U801.4
N114579583: R812.1 U801.5
N114579589: R810.1 U801.6
N114579595: R850.1 U801.7
N114579601: R851.1 U801.8
N114598355: R852.1 U801.9
N114598565: R845.1 U801.10
N114629076: R703.2 R706.2 U701.8
N114629170: R705.2 R710.2 U701.28
N114629402: R818.1 U801.11
N114629754: R707.2 U701.39
N114629773: R708.2 U701.40
N114629886: R715.2 U701.42
N114629887: R714.2 U701.41
N114636326: TP714.1(TP) U701.6
N114797754: D1402.4(CATHODE3) R1423.1
N114797756: D1402.3 R1424.1
N114797758: D1402.1 R1425.1
N114798676: Q1403.1 R1435.1 R1439.2
N114798680: Q1401.1 R1434.1 R1438.2
N114800112: Q1402.1 R1429.2 R1433.1
N114994571: R912.2 U902.5
N114994603: R213.2 R915.2 U902.2
N114997192: R913.1 U902.6
N114999418: D902.A R914.2
N115302368: R839.1 U803.13
N115329910: J1401.15 R854.2
N115331791: J1405.2 J1405.4 R1442.1
N115508226: R841.1 U804.13
N115508248: R840.1 U805.13
N115511669: R829.1 U801.18
N115511689: R833.1 U801.19
N115511709: R832.1 U801.20
N115511729: R835.1 U801.21
N115511749: R858.1 U801.22
N115511769: R836.1 U801.23
N115511789: R837.1 U801.24
N115511922: R821.1 U801.13
N115511942: R825.1 U801.14
N115511962: R860.1 U801.15
N115511982: R826.1 U801.16
N115512059: R831.1 U801.17
N115512397: R822.1 U801.12
N115575393: R303.1 U101.A3
N115646354: C1727.1 D1704.A U1410.5(VOUT)
N115646421: C1728.1 C1729.1 L1703.2 U1706.9
N115646547: C1730.1 U1410.4
N115646842: C1415.1 C1416.1 L1704.2 U1706.4
N115647748: TP1429.1(PIN1) U1706.29
N115647777: TP1951.1(PIN1) U1706.32
N115647791: TP1952.1(PIN1) U1706.33
N115647810: TP1413.1(PIN1) U1706.34
N115647904: D1403.A R1729.1
N115647959: D1404.A R1730.1
N115647999: TP1414.1(PIN1) U1706.40
N115648034: TP1415.1(PIN1) U1706.41
N115648083: TP1416.1(PIN1) U1706.43
N115648105: TP1417.1(PIN1) U1706.44
N115648131: TP1418.1(PIN1) U1706.45
N115648181: TP1419.1(PIN1) U1706.46
N115648263: D1406.A R1421.1
N115648354: D1405.A R1733.1
N115648363: C1431.1 R1737.2 U1706.14
N115648415: R1738.1 U1706.6
N115648419: TP1420.1(PIN1) U1706.55
N115648439: R1422.1 R1734.2 U1405.1
N115648441: R1428.1 R1735.2 TP1431.1(TP) U1405.4
N115648443: R1736.2 R1740.1 TP1432.1(TP) U1405.5
N115648445: TP1421.1(PIN1) U1706.57
N115648473: TP1422.1(PIN1) U1706.58
N115648499: TP1423.1(PIN1) U1706.59
N115648584: R1422.2 R1739.1 TP1430.1(TP) U1405.3
N115648905: R1430.1 U1406.7
N115648976: R1741.1 U1406.5
N115649042: R1743.1 U1406.2
N115649073: Q1404.3 R1742.2 R1744.2 U1407.1
N115649242: D1412.A R1467.2
N115649244: D1413.A R1748.2
N115649263: Q1404.1 R1749.2 R1750.1
N115649426: D1411.A R1464.2
N115649428: D1410.A R1465.2
N115649511: R1751.2 R1753.1 R1755.1 U1407.2
N115649521: R1752.1 R1755.2 U1407.4(Y)
N115650186: R1486.2 R1487.2 U1409.22
N115650188: R1485.2 R1490.1 U1409.18
N115650272: TP1424.1(PIN1) U1409.5
N115650294: TP1425.1(PIN1) U1409.6
N115650321: TP1426.1(PIN1) U1409.7
N115650337: C1449.1 Q1406.3 R1454.1
N115650366: TP1427.1(PIN1) U1409.8
N115650410: C1448.2 C1449.2 Q1406.1 R1449.1 R1756.2
N115650590: TP1428.1(PIN1) U1409.17
N115650809: Q1407.3 R1450.2 R1455.2
N115650811: Q1408.3 R1451.2 R1457.2
N115650813: Q1409.3 R1452.2 R1456.2
N115650815: D1415.A R1453.2
N115650891: D1407.C R1461.1
N115651044: D1415.C(CATHODE) Q1410.3 R1458.2 R1816.2
N115651255: D1414.A Q1411.3 R1468.2
N115651302: J1704.7 R1462.1
N115651381: J1704.9 R1463.1
N115688375: R1057.2 U1708.B2
N115740207: Q301.3 R305.2 R1758.2 U302.A3(\\E\N)
N115740283: R353.2 R358.2 SW301.3
N115740287: R352.1 R356.1 SW301.2
N115740320: R354.2 R359.2 SW301.6(NO2)
N115740338: R355.1 R357.1 SW301.5
N115740452: C304.1 D301.A Q301.1 R1760.2 R1761.1
N115740524: TP305.1(PIN1) U303.C3
N115740681: Q302.3 R1762.2 R1764.2
N115740897: R313.1 U301.5
N115742694: R1766.2 R1772.1 U404.4
N115742746: D302.C(CATHODE) R360.2 R1769.2 R1771.1 U404.3
N115743253: C407.1 U402.A6
N115743279: C409.1 U402.A3
N115743338: R412.2 U402.A2
N115743354: R413.2 R434.2 U402.E1
N115743625: C414.1 D401.C(CATHODE) D402.C(CATHODE) U405.2
N115744998: TP1932.1(PIN1) U411.C3
N115747363: R1780.2 U1712.14
N115747381: R503.2 U1712.13
N115751791: L1705.1 U1710.1 U1710.9
N115751937: C1749.2 R902.2 R1782.1 U1710.3
N115752033: R1783.2 U1710.6
N115752037: C1753.1 U1710.4
N115752085: TP901.1(TP) U1710.7
N115752389: R1784.2 U904.2
N115752394: R946.1 U904.10
N115752439: R1785.2 U904.3
N115752462: R947.1 U904.9
N115752527: R1786.2 U904.4
N115752535: R948.1 U904.8(YB3)
N115752568: R909.2 U904.5
N115752570: R949.1 U904.7
N115753009: D1705.A R1790.1
N115753214: D1706.A R1791.1
N115753489: Q901.3 R918.2 R919.2
N115753655: Q901.1 R958.1 R959.1
N115753665: J1707.62 R932.1
N115754842: J1405.7 R1448.1
N115756645: R1204.2 U1709.E3
N115756807: R1209.2 U1709.G7
N115757278: R1219.2 R1222.1 U1202.4
N115782425: C1321.1 C1322.1 C1323.1 R1329.1 R1814.1 U1306.5(OUT)
N115782532: C1321.2 R1329.2 R1330.1 U1306.4
N115782544: R1333.2 U1306.3
N115782790: R1302.1 U1301.1
N115782792: R1302.2 R1303.2 U1307.2
N115782811: R1324.1 R1325.1 R1326.1 R1327.1 U1309.4(Y)
N115782815: R1324.2 U1301.2
N115783013: R1303.1 U1302.1
N115783041: R1325.2 U1302.2
N115783217: R1318.1 U1304.1
N115783219: R1318.2 R1322.2 U1308.2
N115783240: R1326.2 U1304.2
N115783428: R1322.1 U1305.1
N115783445: R1327.2 U1305.2
N115785368: R601.2 SW601.2
N115785370: R602.2 SW601.4
N115785372: R603.2 SW601.6
N115785374: R604.2 SW601.8
N115788648: D601.A R613.2
N115837191: TP504.1(PIN1) U501.K5
N115863629: R508.1 U1712.39
N115865392: R1795.2 U1709.F2
N115871876: R1203.2 U1709.G1
N115938225: C1204.1 C1205.1 C1230.1 L1205.2 U1709.A2 U1709.C2
N115938370: R1800.1 U1709.B4
N115938505: C1207.1 C1209.1 C1764.1 C1765.1 L1201.2 U1709.C6 U1709.D6 U1709.G2 U1709.G4
N115954867: C1769.2 R1798.1
N115954870: C1770.2 R1801.1
N115959933: C1210.1 U1709.C5
N115991118: Q902.3 R953.2 R954.1 R1813.2 U904.12
N116057568: TP1953.1(PIN1) U1709.F7(XTO)
N116084647: R1718.1 U1713.5
N116084649: R1723.1 U1713.8
N116084651: R1717.1 U1713.4
N116084659: R1724.1 U1713.9
N116084661: R1719.1 U1713.1
N116086427: R1817.2 U1713.15
N116086430: R1818.2 U1713.14
N116086433: R1819.2 U1713.13
N116086500: R1820.2 U1713.12
N116087925: R1821.1 U1713.16
N116088365: R1720.1 U1713.6
N116088374: R1721.1 U1713.7
N116165116: J1707.64 R956.1 R957.1
N116167004: C1023.1 C1024.1 R1083.2 U1004.15
N116167167: D1012.C(CATHODE) R1072.1
N116167227: C1022.1 R1082.2 U1004.16
N116167406: R1077.2 U1004.1
N116167434: R1073.2 R1080.2 U1004.2
N116167436: R1074.2 R1081.2 U1004.5
N116167463: R1076.2 R1084.2 R1085.1 TP1020.1(PIN1) U1004.12
N116167513: R1078.2 U1004.3
N116167550: R1079.2 U1004.4
N116167586: TP1015.1(PIN1) U1004.8
N116167598: TP1016.1(PIN1) U1004.9
N116167606: TP1017.1(PIN1) U1004.10
N116167616: TP1018.1(PIN1) U1004.11
N116227167: J1710.1 R745.1
N116260997: R863.2 TP1954.1(TP) U915.C1
N116323997: D1011.C(CATHODE) R1083.1
N116421020: R211.1 U201.A8
N116438273: R719.2 U701.24
N116438275: R717.2 U701.25
N116438398: R713.1 U701.27
N116438407: R712.1 U701.26
N116439658: R1824.1 R1825.2 U1714.4
N116441929: R1827.2 TP45.1(PIN1) U58.3
N116441950: C10.1 R14.1 R16.2 U58.4
N116479778: R102.2 U201.G11
N116481485: R930.1 U908.2
N116482975: R931.1 U908.3
N116484883: R743.2 R744.1 R746.1 U908.12
N116485241: R432.2 U908.9
N116561239: R433.2 U908.10
N116562204: R741.1 U908.8
N116562207: R751.1 U908.7
N116562556: R742.1 U908.4
N116562559: R752.1 U908.5

Pads without a net: J1101 A2 A3 A10 A11 B2 B3 B10 B11; J1201 6; J1707 44 46 48 59 61 65 66 67 68 70 71 73; J1708 A2 A3 A8 A10 A11 B2 B3 B8 B10 B11; SW301 1 4; U201 A1 A2 A11 A12 AA1 AA2 AA4 AA9 AA11 AA12 AB1 AB2 AB11 AB12 B1 B12 K5 K8 N5 N8 P2 P4 P5 P8 P9 P11 R2 R3 R4 R9 R10 R11 T2 U2 U4 U9 U11 V2 V3 V4 V9 V10 V11 W3 W10 Y2 Y3 Y4 Y9 Y10 Y11; U303 D1 D2; U411 D1 D2; U501 A1 A2 A7 A8 A9 A10 A11 A12 A13 A14 B1 B7 B8 B9 B10 B11 B12 B13 B14 C1 C3 C5 C7 C8 C9 C10 C11 C12 C13 C14 D1 D2 D3 D4 D12 D13 D14 E1 E2 E3 E5 E8 E9 E10 E12 E13 E14 F1 F2 F3 F10 F12 F13 F14 G1 G2 G3 G10 G12 G13 G14 H1 H2 H3 H12 H13 H14 J1 J2 J3 J12 J13 J14 K1 K2 K3 K6 K7 K10 K12 K13 K14 L1 L2 L3 L12 L13 L14 M1 M2 M3 M7 M8 M9 M10 M11 M12 M13 M14 N1 N3 N6 N7 N8 N9 N10 N11 N12 N13 N14 P1 P2 P7 P8 P9 P10 P11 P12 P13 P14; U802 1; U804 10 11 12; U901 4; U1307 1; U1308 1; U1309 1; U1407 5; U1702 10 11 12; U1709 C4 D5 E5 E6 E7 F4 F5

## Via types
v1: diameter 0.406, hole 0.203, TOP to BOTTOM, 1841 vias
v2: diameter 0.508, hole 0.257, TOP to BOTTOM, 53 vias

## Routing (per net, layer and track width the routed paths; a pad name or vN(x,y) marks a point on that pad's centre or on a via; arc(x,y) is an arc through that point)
5V_PG: length 4.1
  TOP w0.254: U901.3 40.94,33.08 41.81,32.21 TP903.1
GND: length 854.8
  TOP w0.076: U1709.F3 104.77,29.07 104.77,29.34 ; 102.26,38.65 102.74,38.65 U501.N2 102.74,38.15 102.32,38.15 v1(102.04,38.43) 102.26,38.65
  TOP w0.081: 104.77,29.34 104.77,29.48 104.84,29.54
  TOP w0.152: U1709.D7 101.76,27.82 v1(101.58,28.01) ; v1(103.03,29.96) 103.52,29.46 U1709.G5 ; 104.84,29.54 v1(105.08,29.79) ; v1(101.56,26.96) 101.64,26.96 102.01,27.32 U1709.C7
  TOP w0.203: U501.C4 104.04,43.4 104.47,42.97 v1(104.56,42.97) ; v1(108.95,71.43) 109.18,71.21 U805.6 ; U101.K9 v1(88.49,52.71) U101.H9 ; U101.M8 v1(87.49,51.21) ; v1(87.49,51.21) U101.M6 ; v1(87.49,51.21) U101.L7 ; U904.6 v1(127.01,24.62) ; v1(90.49,54.71) U101.E12 ; U501.E7 v1(105.48,42.01) ; v1(104.86,37.44) 104.98,37.56 U501.P6 U501.N5 ; v1(91.49,52.71) U101.H15 v1(91.49,53.7) U101.F15 v1(91.49,54.7) U101.D15 ; U101.M12 v1(89.49,51.21) U101.M10 U101.N10 v1(89.49,50.71) ; v1(103.83,37.3) 103.83,37.35 103.98,37.51 U501.P4 ; U803.6 131.42,72.94 v1(131.63,73.16) ; U1709.B1 105.67,26.82 v1(105.85,26.64) ; v1(60.36,31.94) 60.36,31.79 60.6,31.55 U701.5 ; D1009.2 v1(123.35,58.93) ; D1005.2 v1(123.31,56.9) ; v1(86.5,55.71) U101.C6 v1(87.49,55.71) U101.C8 ; R424.2 89.74,65.32 v1(89.63,65.43) ; D1006.2 123.59,52.83 v1(123.72,52.7) ; TP1908.1 v1(56.26,33.22) ; v1(74.46,52.04) 74.46,52.08 U201.G5 ; U201.G8 74.49,50.36 v1(74.49,50.45) ; U101.F10 v1(88.49,54.21) U101.F8 v1(87.49,54.21) U101.F6 U101.G6 86.99,53.2 v1(86.97,53.18) 86.99,53.16 U101.J6 ; U101.P15 v1(91.49,50.71) U101.M15 v1(91.49,51.7) ; v1(104.86,40.46) 104.8,40.4 U501.J5 ; v1(30.16,9.94) 29.72,9.5 U403.B1 ; D1007.2 123.56,51.17 v1(123.66,51.27) ; v1(104.11,41.33) 104.18,41.4 U501.G5 ; U101.R8 v1(87.49,49.71) U101.R6 v1(86.49,49.71) U101.R4 85.99,49.71 v1(85.49,49.71) U101.P3 v1(85.49,50.71) U101.M3 v1(85.49,51.71) U101.K3 v1(85.49,52.71) U101.H3 v1(85.49,53.71) U101.F3 v1(85.49,54.71) U101.D3 ; U101.J12 89.99,53.07 90.03,53.11 90.03,53.17 v1(90.04,53.17) 90.03,53.17 89.99,53.22 U101.G12 ; U101.C12 v1(90.49,55.71) U101.C14 ; v1(33.82,20.01) 33.94,19.88 U411.B3 ; U101.R14 v1(90.49,49.71) U101.R12 ; U801.25 106.51,63.32 v1(106.27,63.08) 106.53,62.82 U801.26 ; U201.G1 v1(74.13,56.2) ; v1(35.3,18.71) 35.3,18.96 35.1,19.17 U411.D3 ; R303.2 83.21,61.03 v1(83.13,61.1) ; U804.6 99.26,71.73 99.06,71.92 v1(98.99,71.92) ; U501.K8 105.98,39.48 v1(105.94,39.44) ; v1(107.39,40.9) U501.H10 ; J1101.SH1 23.96,6.75 v1(23.91,6.8) ; v1(84.25,57.1) 84.25,56.95 U101.A1 ; v1(105.21,44.73) 104.98,44.51 U501.A6 ; U303.B3 71.4,11.36 v1(71.18,11.14) ; D1010.2 v1(123.29,57.91) ; U101.U17 v1(92.79,48.41) ; v1(17.93,7.77) 18.06,7.64 J1708.A12 18.06,6.24 J1708.B1 ; U303.D3 71.38,12.16 v1(71.21,12.33) ; D1008.2 123.59,50.2 v1(123.76,50.02) ; U1708.B1 v1(129.92,45.13) ; J1708.B12 12.56,6.24 J1708.A1 12.56,7.66 v1(12.67,7.77) ; U101.A17 v1(92.82,57.03) ; v1(106.37,27.14) 106.19,27.32 U1709.C1 ; U701.43 v1(68.15,34) ; U101.R10 v1(88.48,50.22) ; U1403.B1 v1(15.91,9.5)
  TOP w0.254: R507.2 77.85,23.17 v1(77.62,23.39) ; R1745.2 v1(20.54,59.54) ; U201.Y1 65.68,55.68 v1(65.35,56.01) ; C521.2 v1(79.45,23.29) ; U1401.7 121.88,67.73 v1(122.12,67.97) ; v1(67.95,46.4) 68.28,46.73 U201.T12 ; v1(65.35,46.4) 65.68,46.73 U201.Y12 ; v1(67.95,52.81) 68.28,52.48 U201.T5 ; v1(65.35,52.81) 65.68,52.48 U201.Y5 ; v1(31.21,62.23) 31.02,62.43 U1404.10 ; v1(59.25,25.57) 59.34,25.66 C717.2 ; v1(119.08,8.05) 119.35,7.78 J1707.57 ; v1(31.27,62.85) 31.25,62.83 U1404.11 ; v1(86.53,64.46) 86.19,64.8 84.96,64.8 C401.2 ; v1(26.07,7.1) 26.12,7.05 J1101.A1 26.68,6.24 J1101.B12 ; v1(24.65,69.86) 24.77,69.98 U1702.6 ; U503.3 84.71,21.37 v1(84.6,21.26) ; U201.J3 72.49,54.34 72.49,54.38 v1(72.45,54.43) ; v1(66,48.8) 66.33,49.13 U201.W9 ; U201.W2 66.33,54.88 v1(66,55.21) ; v1(65.35,49.6) 65.68,49.93 U201.Y8 ; U1706.25 18.08,27.87 v1(18.23,27.72) ; U1706.5 v1(9.5,22.84) ; v1(72.45,46.36) 72.45,46.42 U201.J12 ; v1(66,53.61) 66.33,53.28 U201.W4 ; U201.T3 68.28,54.08 v1(67.97,54.38) ; R1746.2 20.88,62.33 v1(21.16,62.05) ; U1409.24 22.46,53.99 v1(22.23,53.76) 21.96,54.02 U1409.23 ; J1707.7 v1(131.85,8.02) ; v1(75.43,51.82) 75.43,51.82 U201.E5 ; v1(27.12,58.72) 27.33,58.51 R1728.2 ; C520.2 v1(81.41,23.36) ; U201.K4 v1(71.83,52.86) ; J1707.39 123.85,7.98 v1(123.81,8.02) ; Q301.2 v1(74.71,15.87) ; v1(71.79,55.16) 71.82,55.16 U201.K2 ; v1(64.05,48) 64.38,48.33 U201.AB10 ; v1(73.82,53.66) 73.82,53.69 U201.G3 ; v1(78.54,48.4) 78.53,48.41 U201.A10 ; U1706.51 6.49,30.37 v1(6.68,30.56) ; v1(75.79,47.97) 75.79,47.9 U201.D11 ; U401.5 38.52,15.57 v1(38.85,15.24) ; v1(14.35,52.35) 14.35,52.53 TP617.1 ; v1(114.78,8.02) 114.85,7.94 J1707.75 ; v1(8.76,48.35) 8.91,48.51 U1713.11 ; U201.E1 75.43,56.12 v1(75.58,56.26) ; v1(13.65,22.87) 13.5,22.72 U1706.13 ; U201.J10 72.52,48.1 v1(72.52,48.07) 72.18,47.72 U201.K11 ; J1707.33 v1(125.35,8.09) ; C1509.2 v1(44.96,70.32) ; v1(68.61,48.8) 68.28,48.48 U201.T10 ; U1706.1 v1(7.5,22.84) ; v1(67.29,52.06) 67.29,52.1 U201.V5 ; U201.C8 77,50.27 v1(77,50.34) ; v1(67.95,49.6) 68.28,49.93 U201.T8 ; U502.8 U502.3 v1(89.15,21.26) ; J1707.1 133.35,8.01 v1(133.34,8.02) ; v1(76.71,9.36) 76.71,9.33 76.4,9.02 U1302.8 76.02,7.91 75.58,8.36 U1302.3 75.58,8.86 75.15,9.29 U1302.7 v1(76.17,9.66) ; v1(66,47.2) 66.33,47.53 U201.W11 ; U201.A3 v1(78.5,54.01) ; J1707.45 v1(122.35,8.02) ; v1(23.71,39.07) 23.66,39.02 U1408.6 ; C412.2 v1(31.12,38.51) ; R1490.2 16.3,56.81 v1(16.22,56.89) ; U1706.47 v1(8,34.46) ; v1(66.65,56.01) 66.98,55.68 U201.V1 ; U101.U1 v1(84.17,48.38) ; U201.P12 69.58,46.73 v1(69.25,46.4) ; v1(19.15,62.34) 19.09,62.29 U1406.4 ; v1(64.05,54.41) 64.38,54.08 U201.AB3 ; J1707.51 v1(120.85,8.1) ; U201.N2 70.23,54.88 69.88,55.23 v1(69.81,55.23) 69.58,55.46 U201.P1 ; U201.AB5 64.38,52.48 v1(64.05,52.81) ; U1706.15 14.5,22.84 v1(14.4,22.94) ; C716.2 v1(59.81,29.04) ; R423.2 v1(81.84,62.51) ; U201.T1 68.28,55.68 68.28,55.68 v1(68.28,56.07) ; v1(76.37,46.42) 76.37,46.45 U201.C12 ; U201.J1 72.83,55.92 72.83,55.92 v1(72.83,56.2) ; v1(123.21,28.98) 123.21,28.98 U906.6 ; v1(69.85,49.61) 69.9,49.61 70.23,49.28 U201.N9 ; J1707.18 129.1,15 v1(129.19,15.09) ; U201.N4 70.23,53.28 69.91,53.6 v1(69.86,53.6) 69.58,53.88 U201.P3 ; v1(71.71,49.2) 72.17,49.2 U201.K9 ; v1(76.99,52.06) 76.99,52.14 U201.C5 ; U1407.3 13.65,68.28 v1(13.34,68.6) ; v1(1.97,31.23) 2.28,31.54 C1422.2 ; U201.V12 66.98,46.73 v1(66.65,46.4) ; U201.D2 75.72,54.44 v1(75.72,54.42) ; U1706.11 12.5,20.92 v1(12.75,20.67) ; U201.AB8 64.38,49.93 v1(64.05,49.6) ; v1(73.57,6.48) 73.9,6.82 U1302.6 ; U201.G12 74.13,46.6 73.88,46.35 v1(73.85,46.35) ; v1(21.64,59.19) 21.46,59.01 U1409.9 ; U1713.10 v1(8.75,48.91) ; v1(73.82,48.02) 73.82,48.1 U201.G10 ; U503.8 v1(84.71,23.57) ; v1(76.41,55.95) 76.41,55.92 U201.C1 ; v1(66.65,49.6) 66.98,49.93 U201.V8 ; U201.N11 70.23,47.68 v1(69.9,48) 69.58,48.33 U201.P10 ; J1707.63 v1(117.85,8.13) ; v1(19.2,24.85) 19.59,25.25 C1420.2 ; v1(37.36,34.95) 37.49,34.82 U901.10 ; U201.E8 v1(75.43,50.44) ; U1401.6 v1(122.11,67.23) ; C1738.2 v1(82.55,23.36) ; J1707.69 v1(116.35,8.09) ; U902.4 50.21,40 v1(50.14,39.93) ; C1421.2 v1(1.92,33.82) ; U201.E12 v1(75.43,46.3) ; U1706.35 v1(14,34.53) ; U1302.5 v1(75.15,5.64) ; R415.2 v1(81.82,63.62) ; U1707.3 v1(132.93,40.86) ; U1706.10 12,22.75 v1(11.87,22.88) ; v1(76.39,52.86) 76.39,52.9 U201.D4 ; v1(76.38,49.54) 76.38,49.51 U201.D9 ; U1702.13 v1(26.1,73)
  TOP w0.305: v1(12.67,74.81) 12.67,74.49 C1323.2 ; C1303.2 16.55,75.3 v1(16.71,75.45) ; v1(14.33,73.11) 13.52,73.11 C1322.2 ; R718.2 v1(73.04,25.42) ; U404.2 v1(24.62,30.69) ; v1(58.83,32.29) 58.92,32.37 C727.2 ; C1302.2 v1(16.38,73.02) ; C728.2 v1(58.7,33.3)
  TOP w0.381: R353.1 v1(71.85,7.61) ; SW1402.2 v1(34.55,80.74) ; C1460.2 19.1,51.77 v1(18.54,51.2) ; v1(83,41.59) 83.36,41.95 R405.2 ; v1(28.44,66.63) 28.09,66.98 C1503.2 ; X1401.2 4.93,15.96 v1(4.85,15.88) ; v1(1.96,67.34) 2.17,67.55 D601.C ; C913.2 111.08,12.85 v1(111.66,13.43) ; C1325.2 16.79,75.54 v1(16.71,75.45) ; U1307.3 v1(19.42,74.18) ; U1305.8 v1(76.4,80.22) ; J1401.25 v1(118.67,74.22) ; v1(96.16,18.7) 96.16,19.2 R509.1 97.25,19.13 v1(97.25,18.7) ; v1(5.26,66.36) 5.57,66.36 R1754.2 ; v1(86.52,74.04) 86.56,74.01 R1433.2 ; R1448.2 v1(47.84,63.63) ; J1101.B1 32.18,6.24 J1101.A12 32.18,7.92 v1(32.19,7.93) ; J1401.20 v1(111.05,79.17) ; v1(16.66,68.52) 16.91,68.27 Q1404.2 ; C513.2 95.04,37.46 v1(94.79,37.71) ; R1488.2 13.95,10.53 v1(13.59,10.88) ; R1412.1 v1(121.88,62.73) ; v1(35.47,56.07) 35.59,56.19 R612.2 ; v1(16.81,71.6) 17.17,71.25 C1324.2 ; U1309.3 v1(20.81,78.05) ; Q1408.2 v1(19.86,64.1) ; C1504.1 v1(39.48,70.31) ; TVS1401.1 12.79,11.06 v1(13.63,11.9) ; C1308.2 v1(76.63,0.71) ; v1(25.03,80.81) 24.96,80.74 SW1401.1 ; v1(99.57,14.61) 99.33,14.37 TVS1203.1 ; C1423.2 v1(19.69,31.47) ; v1(104.39,22.91) 104.35,22.95 R1800.2 ; C1462.2 v1(18.88,79.87) ; C1752.2 133.1,37.35 v1(132.71,37.74) ; C305.2 v1(71.12,8.03) ; R1747.2 v1(12.6,61.82) ; C1748.2 v1(134.09,29.62) ; C1019.2 v1(137.15,43.51) ; Q902.2 134.59,24.23 v1(134.77,24.05) ; R1330.2 v1(8.69,72.63) ; Q901.2 119.29,24.23 v1(119.14,24.38) ; R840.2 v1(115.19,70.31) ; SW1401.2 v1(29.19,80.74) ; R1770.2 26.8,26.74 v1(27.32,26.23) ; C1310.2 v1(7.68,74.67) ; C1719.2 v1(15.15,46.4) ; R508.2 v1(82.91,27.11) ; J1704.5 v1(28.21,50.12) ; v1(35.47,49.48) 35.47,49.48 R609.2 ; Q1402.2 v1(84.2,73.51) ; C1720.2 15.09,47.33 v1(15.12,47.36) ; R611.2 35.67,55.09 v1(35.36,55.39) ; v1(35.26,35.25) 35.68,35.67 C907.2 ; v1(125.03,44.02) 125.48,44.02 C1020.2 125.35,44.76 v1(125.04,44.76) ; v1(105.36,14.56) 105.17,14.37 TVS1204.1 ; R911.2 v1(44.96,36.12) ; v1(53,24.16) 53.06,24.09 Q302.2 ; v1(134.92,38.59) 134.92,38.19 C1750.2 134.19,38.14 v1(134.19,38.65) ; C1301.2 v1(7.77,8.46) ; D902.C 49.92,29.73 v1(49.93,29.74) ; v1(53.86,35.87) 53.53,35.87 C928.2 53.55,36.65 v1(53.92,36.65) ; v1(42.74,10.47) 42.74,11.7 C301.2 41.63,11.68 v1(41.63,10.51) ; J1002.6 v1(126.4,51.7) ; v1(127.12,42.16) C1731.2 ; R1222.2 112.47,33.27 v1(111.56,34.18) ; v1(58.95,64.48) 59.67,64.48 C1414.2 ; TP615.1 v1(31.54,11.25) ; C1733.2 23.11,36.53 v1(22.74,36.16) ; C1403.2 125.22,66.66 v1(125.26,66.7) ; C903.2 v1(46.26,43.83) ; U802.3 v1(101.59,64.26) ; C309.1 69.34,9.7 v1(69.02,9.38) ; C510.2 81.33,31.47 Y501.2 v1(81.29,32.31) ; v1(102.04,21.76) 102.39,22.12 C1763.2 ; R838.2 132.61,67.62 C804.2 131.47,67.3 131.09,66.92 v1(131.09,66.92) ; v1(75.15,81.01) U1305.7 75.58,80.08 U1305.3 ; C1435.2 19.1,36.74 C1434.2 18.97,36.1 v1(19.23,35.84) ; C1430.2 6.14,19.75 v1(6.43,19.47) ; R1795.1 v1(108.68,32.49) ; R1738.2 v1(10.08,18.24) ; v1(46.3,38.55) C904.2 v1(44.69,37.71) ; D901.A 49.23,5.94 v1(48.85,6.31) ; C519.2 86.25,39.59 v1(86.18,39.52) ; D1410.C 2.17,57.01 v1(1.93,57.25) ; U1304.8 5.56,77.71 v1(6.06,77.21) ; v1(25.93,64.44) 26.28,64.09 C1427.2 26.55,63.2 C1426.2 ; v1(32.04,33.17) 31.99,33.12 C414.2 ; R527.2 90.97,37.63 v1(91.1,37.75) ; v1(82.56,29.03) 82.72,29.18 C517.2 C516.2 ; C1732.2 123.38,55.47 v1(123.16,55.69) ; C1320.2 v1(12.5,80.89) ; U1304.5 4.31,76.52 v1(4.29,76.5) ; C1461.2 v1(20.5,51.56) ; C1319.2 v1(10.37,81.29) ; v1(1.83,62.97) 2.17,62.63 D1414.C ; v1(43.08,75.5) 43,75.58 C1506.2 ; C1787.1 99.23,28.74 C1209.2 98.98,27.76 v1(99.2,27.54) ; v1(4.11,81.17) 4.31,80.97 U1304.7 ; v1(125.09,70.09) C1401.2 v1(125.83,69.22) ; v1(25.7,28.66) 25.86,28.82 R1771.2 ; C1756.2 v1(132.24,23.71) ; U1501.2 30.26,76.02 v1(30.09,76.19) ; v1(128.52,79.1) 128.83,79.41 J1401.34 ; R1446.2 v1(47.85,67.79) ; v1(71.47,16.26) 71.4,16.33 R1761.2 ; D1503.3 v1(45.25,76.42) ; C1208.2 v1(107.06,17.57) ; v1(19.2,40.84) 18.97,40.61 C1436.2 19.1,39.98 C1437.2 ; v1(45.97,7.58) 46.16,7.4 J301.A12 ; v1(94.02,37.68) C514.2 R523.2 ; C916.2 110.68,5.96 v1(110.68,6.62) ; J1401.9 v1(98.35,78.51) ; R1821.2 12.1,44.98 v1(12.45,44.98) ; v1(85.89,37.68) C1740.2 C1739.2 ; v1(117.83,27.98) 117.99,27.82 C923.2 ; R1782.2 v1(129.43,37.32) ; TP1904.1 v1(93.79,22.2) ; C1424.2 26.38,61.84 26.52,61.7 C1425.2 v1(25.9,60.97) ; v1(3.84,43.29) 3.72,43.41 U1405.2 ; U1305.6 v1(73.32,78.76) ; v1(100.4,21.75) 100.86,22.21 C1762.2 ; R1462.2 R1463.2 v1(25.27,52.77) ; v1(112.62,13.41) 112.2,12.99 C914.2 ; TP1909.1 v1(48.69,71.53) ; TP1412.1 v1(9.11,7.53) ; C1433.2 v1(10.86,67.44) ; C731.2 v1(59.89,37.2) ; C304.2 71.5,13.65 v1(71.39,13.54) ; C1755.2 v1(131.7,26.26) ; J1401.30 v1(123.75,79.17) ; R827.2 117.94,62.58 v1(117.94,62.66) ; R1759.2 v1(50.46,25.21) ; U405.3 v1(32.02,34.97) ; C1743.2 94.33,27.69 v1(94.68,28.03) ; v1(52.24,30.24) 52.24,30.79 C910.2 51.14,30.77 v1(51.14,30.24) ; Q1410.2 v1(9.1,57.29) ; v1(36.08,6.76) 36.08,6.33 36.54,5.86 36.98,6.29 v1(36.98,6.75) ; C1432.2 v1(12.52,59.14) ; J1704.3 v1(29.48,50.12) ; C1754.2 127.75,34.07 v1(127.62,34.2) ; C1411.2 v1(22.99,80.57) ; v1(74.04,76.62) 74.42,77.01 U1305.5 ; J1002.12 v1(136.81,62.7) ; v1(89.05,37.79) 88.94,37.68 R525.2 ; R1781.2 v1(127.82,30.79) ; v1(131.83,44.76) 132.21,45.13 D1003.2 ; J1002.10 v1(124.65,47.2) ; R1435.2 v1(75.99,73.12) ; R1719.2 v1(14.93,45.3) ; C1771.2 v1(103.46,15.62) ; v1(63.48,6.3) 63.96,5.82 R354.1 ; R1772.2 v1(26.32,36.4) ; R520.2 R521.2 82.52,34.24 v1(81.93,34.24) ; C1508.2 v1(47.23,64.32) ; R1810.2 v1(106.14,18.05) ; C1415.2 v1(6.61,18.37) ; D302.A 27.12,32.21 v1(27.1,32.19) ; C1413.2 v1(59.1,68.45) ; C1318.2 C1317.2 73.93,75.71 v1(73.76,75.89) ; v1(65.69,16.29) 65.76,16.36 R313.2 66.32,16.34 C306.1 ; C1416.2 v1(7.12,19.6) ; R1750.2 v1(19.58,67.55) ; C1217.2 C1223.2 110.22,24.62 v1(110.28,24.68) ; R910.2 v1(35.35,34.25) ; U1410.2 v1(7.1,13.29) ; R522.2 v1(91.99,37.68) ; C1428.2 v1(3.26,20.03) ; R1801.2 v1(107.01,21.36) ; C1728.2 v1(14.22,18.49) ; C1227.1 C1221.1 v1(109.76,21.97) ; R524.2 87.93,37.61 v1(87.77,37.76) ; C1307.2 v1(75.29,0.71) ; C1309.2 v1(4.36,81.85) ; TVS1201.1 v1(108.5,14.61) ; C1721.2 v1(15.13,48.2) ; v1(29.32,78.55) 29.31,78.54 C1501.2 C1502.2 ; v1(2.35,8.12) 2.56,7.91 U1301.6 ; v1(97.37,68.49) 97.39,68.46 C802.2 ; v1(136.87,38.62) 136.87,38.16 C1751.2 136.05,38.26 v1(136.05,38.66) ; C1729.2 v1(13.61,19.64) ; v1(26.07,75.97) C1704.2 C1703.2 24.91,75.35 v1(24.5,75.76) 24.06,75.32 R1706.2 ; Q1411.2 v1(8.01,60.91) ; C921.2 v1(117.78,30.42) ; C1304.2 v1(7.59,6.22) ; J1002.11 v1(136.86,47.2) ; v1(103.49,65.96) 103.96,65.49 C803.2 ; R519.2 v1(81.93,36.17) ; C1409.2 v1(11.3,12.08) ; D1411.C 2.17,50.56 v1(1.88,50.85) ; Q1403.2 v1(80.2,72.05) ; C1737.1 v1(36.65,13.72) ; C1723.2 v1(4.33,21.63) ; v1(49.42,42.91) 49.73,42.6 C908.2 C911.2 ; J1406.7 v1(69.6,79.58) ; R526.2 v1(89.96,37.68) ; R1717.2 v1(14.92,50.15) ; R1823.2 v1(101.98,18.12) ; J1406.8 v1(69.6,74.16) ; v1(130.19,66.92) 130.45,67.19 C807.2 129.57,67.62 R839.2 ; TVS901.1 v1(51.96,5.95) ; J1002.13 v1(124.6,61.8) ; C1404.2 v1(125.22,67.82) ; R1753.2 v1(12.36,70.44) ; J1401.14 v1(103.43,79.17) ; v1(4.31,5.66) U1301.5 ; U1202.2 v1(112.19,30.28) ; U1306.2 v1(10.95,77.17) ; Q1405.2 10.16,66.83 v1(10.24,66.76) ; R841.2 v1(105.41,70.51) ; C413.1 v1(35.36,21.51) ; v1(54.29,77.15) 54.29,77.21 54.34,77.26 R1436.2 ; C1201.2 105.49,32.36 v1(105.61,32.49) ; TVS1202.1 102.94,14.38 v1(102.73,14.59) ; C906.2 v1(52.77,6.32) ; v1(2.78,19.39) 2.73,19.33 X1401.4 ; R1447.2 v1(47.83,65.46) ; TP1902.1 v1(35.35,71.11) ; U1301.7 v1(4.31,10.29) ; D1004.2 v1(119.17,47.01) ; v1(76.07,82.29) Q1401.2 75.42,83.99 R1434.2 ; J1401.6 v1(93.27,79.17) ; C730.2 v1(58.62,34.52) ; v1(77.28,16.11) 77.28,16.73 C1744.1 76.27,16.64 v1(76.27,16.18) ; C1431.2 v1(15.43,17.96) ; C1507.2 v1(38.64,64.2) ; Y501.4 v1(79.74,28.74) ; C1725.2 v1(11.3,13.42) ; TP1907.1 v1(19.65,33.24) ; R610.2 v1(35.47,51.7) ; C1726.2 v1(11.41,14.55) ; v1(44.19,33.32) 44.39,33.52 C902.2 ; C1741.2 v1(82.56,29.77) ; U1301.8 v1(6.07,7.91) ; R418.2 v1(49.84,45.19) ; R1489.2 17.02,10.07 v1(16.59,10.5) ; C1772.2 v1(104.56,15.62) ; R1409.1 v1(119.99,63.24) R1410.1 ; C1210.2 v1(98.3,21.84) ; TP1903.1 v1(10.64,56.13) ; C805.2 114.81,71.92 C806.2 114.83,72.53 v1(114.86,72.56) ; Q1407.2 v1(11.01,60.85) ; C729.2 v1(61.38,37.21) ; R954.2 v1(132.31,26.81) ; C1722.2 v1(15.13,49.16) ; C1412.2 v1(62.88,72.24) ; R1437.2 v1(55.39,77.03) ; C1505.2 v1(41.95,75.49) ; v1(36.6,82.98) 36.87,82.71 C1410.2 ; v1(40.27,32.66) 39.99,32.94 U901.2 ; v1(84.72,25.93) C1742.2 ; J301.B12 v1(40.66,7.48) ; Q1409.2 v1(18.96,18.56) ; U1304.6 v1(2.55,78.76) ; R1798.2 v1(101.02,21.24) ; U1308.3 v1(19.95,70.78) ; SW1402.1 v1(31.94,80.74) ; R413.1 v1(31.64,17.15)
  TOP w0.508: J1401.39 136.45,77.25 v1(138.09,78.89) v1(138.09,81.22) 138.09,84.32 v1(136.71,85.7) v1(134.13,85.7) v1(131.89,85.7) v1(129.26,85.7) v1(127.16,85.7) v1(124.8,85.7) v1(122.78,85.7) v1(120.61,85.7) v1(118.66,85.7) v1(117.15,85.7) v1(114.99,85.7) v1(112.55,85.7) v1(110.07,85.7) v1(107.57,85.7) v1(105.26,85.7) v1(103.12,85.7) v1(100.56,85.7) v1(98.24,85.7) v1(96.18,85.7) v1(94.31,85.7) v1(92.62,85.7) v1(90.86,85.7) v1(88.98,85.7) v1(86.53,85.7) v1(84.54,85.7) v1(82.23,85.7) v1(80.12,85.7) v1(78.38,85.7) v1(76.64,85.7) v1(74.46,85.7) v1(72.23,85.7) v1(70.02,85.7) v1(67.8,85.7) v1(65.67,85.7) v1(63.53,85.7) v1(61.72,85.7) v1(59.28,85.7) v1(57.19,85.7) v1(55.37,85.7) v1(53.12,85.7) v1(50.95,85.7) v1(48.99,85.7) v1(47.12,85.7) v1(45.39,85.7) v1(43.58,85.7) v1(41.83,85.7) v1(40.07,85.7) v1(38.38,85.7) v1(36.26,85.7) v1(34.16,85.7) v1(31.87,85.7) v1(29.6,85.7) v1(27.29,85.7) v1(24.85,85.7) v1(22,85.7) v1(19.08,85.7) v1(16.78,85.7) v1(13.72,85.7) v1(11.05,85.7) v1(8.13,85.7) v1(5.9,85.7) v1(3.33,85.7) 1.73,85.7 0.82,84.78 v1(0.82,83.87) v1(0.82,82.3) v1(0.82,80.85) v1(0.82,79) v1(0.82,76.95) v1(0.82,74.94) v1(0.82,72.74) v1(0.82,70.38) v1(0.82,68.33) v1(0.82,66.54) v1(0.82,64.35) v1(0.82,62.21) v1(0.82,60.46) v1(0.82,58.6) v1(0.82,56.74) v1(0.82,54.28) v1(0.82,52.12) v1(0.82,50.23) v1(0.82,47.54) v1(0.82,45.54) v1(0.82,43.65) v1(0.82,40.77) v1(0.82,38.25) v1(0.82,35.66) v1(0.82,32.39) v1(0.82,29.14) v1(0.82,26.09) v1(0.82,23.01) v1(0.82,20.9) v1(0.82,18.72) v1(0.82,15.92) v1(0.82,13.62) v1(0.82,9.35) v1(0.82,6.95) v1(0.82,4.6) v1(0.82,3.1) v1(0.82,1.36) ; v1(138.87,3.42) v1(138.87,5.74) v1(138.87,8.3) v1(138.87,10.76) v1(138.87,12.71) v1(138.87,13.88) v1(138.87,15.53) v1(138.87,18.55) v1(138.87,20.97) v1(138.87,23.71) v1(138.87,26.44) 138.87,28.2 v1(138.78,28.29) 138.4,28.68 138.4,31.78 138.9,32.28 v1(138.9,32.66) v1(138.9,34.89) v1(138.9,36.93) v1(138.9,39) v1(138.9,41.33) v1(138.9,43.06) v1(138.9,45.36) v1(138.9,47.57) v1(138.9,49.36) v1(138.9,51.52) v1(138.9,53.88) v1(138.9,56.17) v1(138.9,58.9) v1(138.9,61.71) v1(138.9,64.92) v1(138.9,67.42) v1(138.9,71.37)
  BOTTOM w0.152: C108.2 88.88,52.27 88.49,52.66 v1(88.49,52.71)
  BOTTOM w0.203: v1(68.28,56.07) 68.37,56.07 69.01,56.71 C207.2 ; U915.B1 116.98,77.22 117.24,77.48 v1(117.24,78.52) ; C104.2 88.11,53.83 v1(88.49,54.21) 88.49,54.2 C155.2 ; C1745.2 v1(92.43,33.5) ; Y401.2 88.14,62.68 87.72,63.1 87.72,64.34 86.4,65.66 C405.2 86.4,66.34 86.59,66.52 89.56,66.52 89.85,66.23 C404.2 ; C955.2 114.93,79.36 v1(114.69,79.12) ; v1(90.04,53.17) 90.03,53.17 90,53.21 C145.2 89.78,53.61 89.67,53.73 C107.2 ; C402.2 85,61.79 v1(85.25,61.54) ; C116.2 89.21,50.91 89.42,50.71 v1(89.49,50.71) 89.48,50.7 C129.2 ; v1(87.49,54.21) 87.82,54.21 C144.2 ; v1(92.36,64.16) 92.38,64.13 v1(92.38,63.35) v1(92.38,62.23) ; R204.2 83.95,54.2 84.25,53.91 84.25,53.7 84.49,53.46 C151.2 ; C404.2 90.75,65.88 91.14,65.49 Y401.4 ; C404.2 89.85,65.66 v1(89.63,65.43) ; C119.2 91.86,52.21 91.49,52.58 v1(91.49,52.71) ; C403.2 82.41,62.51 v1(81.84,62.51) ; C102.2 91.07,57.81 v1(91.07,60.99) ; v1(90.49,55.71) 90.39,55.71 89.97,55.29 C101.2 ; v1(91.49,54.7) 91.45,54.75 C130.2 ; U915.A2 115.39,77.62 115.17,77.84 115.17,78.45 v1(115.34,78.63) ; C211.2 71.3,47.26 v1(71.01,46.97) ; C153.2 87.16,55.71 v1(87.49,55.71) ; U905.6 v1(123.21,28.98) ; v1(91.49,51.7) 91.49,51.77 91.09,52.17 C131.2
  BOTTOM w0.254: R208.1 74.3,52.2 v1(74.46,52.04) ; C106.2 89.51,51.23 v1(89.49,51.21) 89.52,51.18 C146.2 ; v1(85.49,50.71) 85.49,50.71 C140.2 84.74,50.71 84.51,50.47 C136.2 ; C503.2 105.98,39.41 v1(105.94,39.44) ; v1(115.34,78.63) 115.35,78.63 C956.2 ; v1(86.98,42.05) C105.2 85.81,42.05 C109.2 ; C139.2 85.48,49.72 v1(85.49,49.71) ; v1(75.43,46.3) 75.37,46.36 C204.2 ; C501.2 107.61,41.11 v1(107.39,40.9) ; v1(75.43,51.82) 75.52,51.91 C221.2 ; C502.2 105.53,41.96 v1(105.48,42.01) ; v1(78.5,54.01) 78.62,53.89 C214.2 ; v1(104.56,42.97) 104.6,43.02 C506.2 ; C509.2 101,43.13 C508.2 v1(101,42.67) ; v1(69.9,48) 69.94,47.97 R201.2 ; v1(78.54,48.4) 78.66,48.51 C208.2 ; R207.1 71.96,52.98 v1(71.83,52.86) ; v1(68.61,48.8) 68.46,48.66 C209.2 ; v1(86.49,49.71) 86.55,49.71 86.94,50.09 C137.2 ; v1(67.95,49.6) 68.01,49.66 C213.2 ; v1(67.95,52.81) 68.03,52.73 C210.2 ; C206.2 69.89,55.14 v1(69.81,55.23) ; C1724.2 12.92,20.84 v1(12.75,20.67) ; v1(76.37,46.42) 76.84,46.42 C216.2 ; C212.2 69.34,46.32 v1(69.25,46.4) ; C115.2 87.44,51.26 v1(87.49,51.21) 87.51,51.23 C110.2 ; C1419.2 v1(10.48,34.51) ; v1(65.35,56.01) 65.2,56.16 C215.2 ; v1(64.05,54.41) 64.11,54.46 C219.2 ; v1(76.41,55.95) 76.83,55.95 C218.2 ; C504.2 103.51,36.65 103.83,36.96 v1(103.83,37.3) 103.86,37.33 103.86,37.69 C505.2 ; v1(67.95,46.4) 67.91,46.36 C205.2 ; v1(85.49,53.71) 85.24,53.46 C151.2 ; v1(68.28,56.07) 68.03,56.31 C201.2 ; C217.2 75.6,50.27 v1(75.43,50.44) ; C411.2 38.91,15.31 v1(38.85,15.24) ; C1417.2 v1(6.58,27.87) ; v1(85.49,52.71) 85.49,52.87 85.83,53.21 C138.2 ; v1(102.39,24.93) 102.39,24.94 C1764.2 ; C118.2 91.76,53.97 v1(91.49,53.7) ; C1408.2 13.58,34.11 v1(14,34.53) ; v1(92.79,48.41) 92.87,48.32 C132.2 ; C111.2 87.49,53.75 v1(87.49,54.21) 87.38,54.21 87.25,54.34 C152.2 ; v1(65.35,46.4) 65.44,46.32 C222.2 ; C1418.2 6.51,30.73 v1(6.68,30.56) ; v1(75.58,56.26) 75.48,56.17 C203.2 ; C507.2 104.9,37.48 v1(104.86,37.44) ; v1(69.86,53.6) 69.75,53.71 C202.2 ; v2(42.42,49.49) 42.47,49.54 U1004.7 ; C220.2 65.42,49.67 v1(65.35,49.6)
  BOTTOM w0.305: C10.2 75.85,77.53 R14.2 v1(77.15,78.07) ; C22.2 113.06,26.3 C1792.2 113.18,26.91 v1(112.95,27.14) ; C23.2 119.64,25.24 v1(119.14,25.74) ; R743.1 v1(117.83,27.98) ; U908.6 116.17,23.03 v1(116.49,22.7) ; U58.2 78.13,73.65 v1(77.9,73.88) ; v1(84.25,57.1) 84.64,56.71 85.47,56.71 C133.2 ; C930.2 v1(80.5,77.98)
  BOTTOM w0.381: v1(6.22,13.26) 5.58,13.26 C1730.2 ; v1(105.18,71.06) 104.71,70.6 C808.2 C809.2 ; v1(117.78,30.42) 118.01,30.18 C920.2 ; v1(84.2,74.24) 84.56,74.24 C38.2 84.65,73.51 v1(84.2,73.51) ; C1023.2 v1(33.4,54.77) ; C1405.2 94.22,79.94 v1(94.41,80.13) ; C801.2 v1(107.07,63.93) ; v1(111.54,6.58) 111.54,6.01 C917.2 ; v1(103.03,29.96) 102.91,29.84 C1765.2 ; C922.2 v1(117.83,27.98) ; R752.2 119.45,23.7 R742.2 119.43,24.09 v1(119.14,24.38) ; U1714.2 v1(97.12,78.72) ; C418.2 34.94,19.07 v1(35.3,18.71) ; BT1001.2 v1(45.43,59.23) ; R741.2 113.67,21.12 R751.2 115.01,21.12 v1(115.59,21.7) ; R1079.1 v1(46.22,50.13) R1078.1 ; v1(105.85,26.64) 105.13,26.64 C1202.2 ; R1812.1 v1(117.83,29.08) ; C512.2 86.11,32.74 C511.2 ; v1(92.36,64.16) 92.23,64.28 Y401.4 ; v1(35.47,51.7) 35.79,52.02 C1021.2 C1024.2 ; v1(130.53,10.39) 130.53,10.88 C918.2 131.56,10.75 v1(131.56,10.34) ; C1727.2 4.57,10.55 v1(4.31,10.29) ; C1219.2 v1(111.36,28.16) ; C1429.2 4.18,42.95 v1(3.84,43.29) ; v1(71.33,15.17) 71.29,15.2 C307.2 ; v1(39.04,58.95) 38.71,58.95 C1022.2 ; C142.2 56.41,22.82 v1(56.75,23.16) ; R1824.2 98.9,75.93 97.45,75.93 v1(97.17,76.21) ; v1(106.37,27.14) 106.48,27.25 C1207.2 105.76,28.13 C1231.2 ; C143.2 57.79,22.8 v1(57.43,23.17) ; Y401.2 88.94,61.58 v1(88.86,61.49) ; C1789.2 v1(102.44,79.17) ; C408.2 v1(29.14,16.66)
  vias: v1(0.84,85.67) v1(1.48,31.84) v1(1.49,30.22) v1(1.56,29.19) v1(1.55,27.95) v1(1.56,26.64) v1(1.57,25.62) v1(1.51,24.53) v1(1.52,23.21) v1(1.57,21.23) v1(1.58,19.92) v1(1.59,18.9) v1(1.55,16.59) v1(1.56,15.27) v1(1.57,14.26) v1(1.64,83.92) v1(1.65,82.3) v1(1.69,48.98) v1(1.69,47.35) v1(1.76,46.12) v1(1.77,44.49) v1(1.93,74.44) v1(1.95,73.52) v1(2.15,84.67) v1(2.39,20.52) v1(3.56,74.45) v1(3.58,73.52) v1(4.13,84.6) v1(5.64,0.78) v1(5.71,1.69) v1(5.99,84.5) v1(6.97,1.7) v1(7.69,0.76) v1(8.3,1.77) v1(9.55,1.77) v1(9.74,0.79) v1(10.13,84.48) v1(10.19,82.27) v1(12.17,1.8) v1(12.1,0.74) v1(14.06,0.78) v1(14.13,1.84) v1(14.94,13.13) v1(15.03,11.73) v1(15.59,0.82) v1(15.66,1.87) v1(16.24,11) v1(17.48,0.9) v1(17.55,1.96) v1(18.88,0.9) v1(20.09,10.48) v1(21.08,0.76) v1(21.77,10.47) v1(21.74,1.77) v1(22.34,0.77) v1(22.99,1.77) v1(24.88,24.79) v1(24.88,23.49) v1(25.72,11.85) v1(26.25,13.05) v1(26.25,0.83) v1(26.36,15.15) v1(26.63,1.73) v1(27.2,12.32) v1(28.09,0.82) v1(28.22,12.35) v1(28.59,1.77) v1(30.04,0.83) v1(30.12,1.8) v1(30.34,12.33) v1(32.01,24.75) v1(32.03,23.51) v1(32.01,1.88) v1(32.45,0.83) v1(34.65,26.19) v1(35.37,0.8) v1(35.66,1.95) v1(36.15,26.23) v1(36.92,1.95) v1(37.37,26.26) v1(37.38,0.81) v1(39.91,0.8) v1(40.81,1.7) v1(41.98,0.77) v1(42.76,1.7) v1(43.92,0.77) v1(44.66,1.73) v1(45.85,26.02) v1(45.83,0.81) v1(46.06,27.82) v1(46.12,1.75) v1(47.29,0.82) v1(47.71,19.19) v1(47.94,30.04) v1(47.94,28.88) v1(48.22,19.21) v1(48.8,24.6) v1(48.78,23.8) v1(48.74,19.19) v1(49.34,0.79) v1(49.87,1.7) v1(50.16,16.69) v1(50.18,15.49) v1(50.92,16.69) v1(50.94,15.49) v1(51.06,0.78) v1(51.59,1.69) v1(52.84,0.79) v1(53.37,1.7) v1(54.16,0.79) v1(55.8,0.82) v1(57.93,0.72) v1(60.14,17.32) v1(60.23,15.41) v1(60.31,0.77) v1(60.9,17.32) v1(60.86,15.4) v1(62.85,21.99) v1(62.88,20.85) v1(62.9,19.64) v1(63.61,21.99) v1(63.64,20.85) v1(63.66,19.64) v1(64.08,0.74) v1(65.3,39.92) v1(65.3,38.68) v1(65.32,41.24) v1(66.27,41.24) v1(66.4,39.88) v1(66.4,38.67) v1(67.64,0.76) v1(70.94,0.77) v1(71.84,52.06) v1(72.72,0.76) v1(74.14,0.76) v1(76.18,30.46) v1(76.2,28.06) v1(76.25,32.09) v1(76.22,26.44) v1(76.94,30.46) v1(76.96,28.06) v1(76.98,26.44) v1(77.02,32.09) v1(78.74,51.67) v1(78.78,50.05) v1(79.72,48.73) v1(80.3,51.02) v1(80.32,49.52) v1(81.28,48.72) v1(82.1,54.29) v1(84.89,79.1) v1(85.49,79.12) v1(107.28,0.85) v1(108.98,0.85) v1(110.71,0.85) v1(112.33,0.86) v1(114.16,0.88) v1(115.87,0.88) v1(117.59,0.88) v1(119.22,0.89) v1(121.09,0.92) v1(122.8,0.92) v1(124.52,0.92) v1(126.14,0.93) v1(128.02,0.84) v1(129.73,0.84) v1(131.45,0.84) v1(133.07,0.85) v1(133.89,32.11) v1(134.08,0.86) v1(134.7,32.11) v1(136.72,66.36) v1(136.73,64.73) v1(137.61,68.25) v1(137.62,66.63) v1(137.63,56.63) v1(137.64,55.01) v1(137.89,75.66) v1(137.9,74.04) v1(137.85,60.57) v1(137.86,58.94) v1(137.81,50.59) v1(137.82,48.97) v1(137.92,64.57) v1(137.93,62.95) v1(137.92,5.75) v1(137.93,4.12) v1(138.71,0.89) v1(138.81,77.66) v1(138.89,75.06) v1(138.87,73.11) v1(138.95,82.94) v1(138.93,80.05) v2(20.4,55.7) v2(20.42,57.23) v2(21.21,56.5) v2(22.02,57.3) v2(22.07,55.68) v2(37.39,17.98) v2(37.41,17.3) v2(38.03,17.98) v2(38.02,17.3) v2(41.36,52.33) v2(41.32,50.87) v2(41.32,49.5) v2(42.46,52.32) v2(42.42,50.87) v2(63.3,31.65) v2(63.27,30.63) v2(63.22,29.57) v2(64.2,31.66) v2(64.17,30.65) v2(64.12,29.58) v2(65.25,31.68) v2(65.3,30.66) v2(65.33,29.57) v2(65.35,28.55) v2(66,31.63) v2(66.21,30.67) v2(66.23,29.58) v2(66.26,28.56) v2(66.99,31.69) v2(67.92,13.13) v2(68.45,13.47) v2(87.27,32.03) v2(87.25,30.15) v2(87.3,31.22) v2(88.27,32.03) v2(88.29,31.22) v2(88.31,30.12) v2(89.26,30.23) v2(89.33,31.24) v2(89.41,32.26) v2(90.23,31.26) v2(90.27,30.28) v2(90.37,32.23) v2(108.79,62.71) v2(108.76,61.65) v2(108.76,60.43) v2(109.88,62.71) v2(109.86,61.67) v2(109.83,60.43) v2(110.8,61.62) v2(110.85,62.74) v2(110.82,60.4)
